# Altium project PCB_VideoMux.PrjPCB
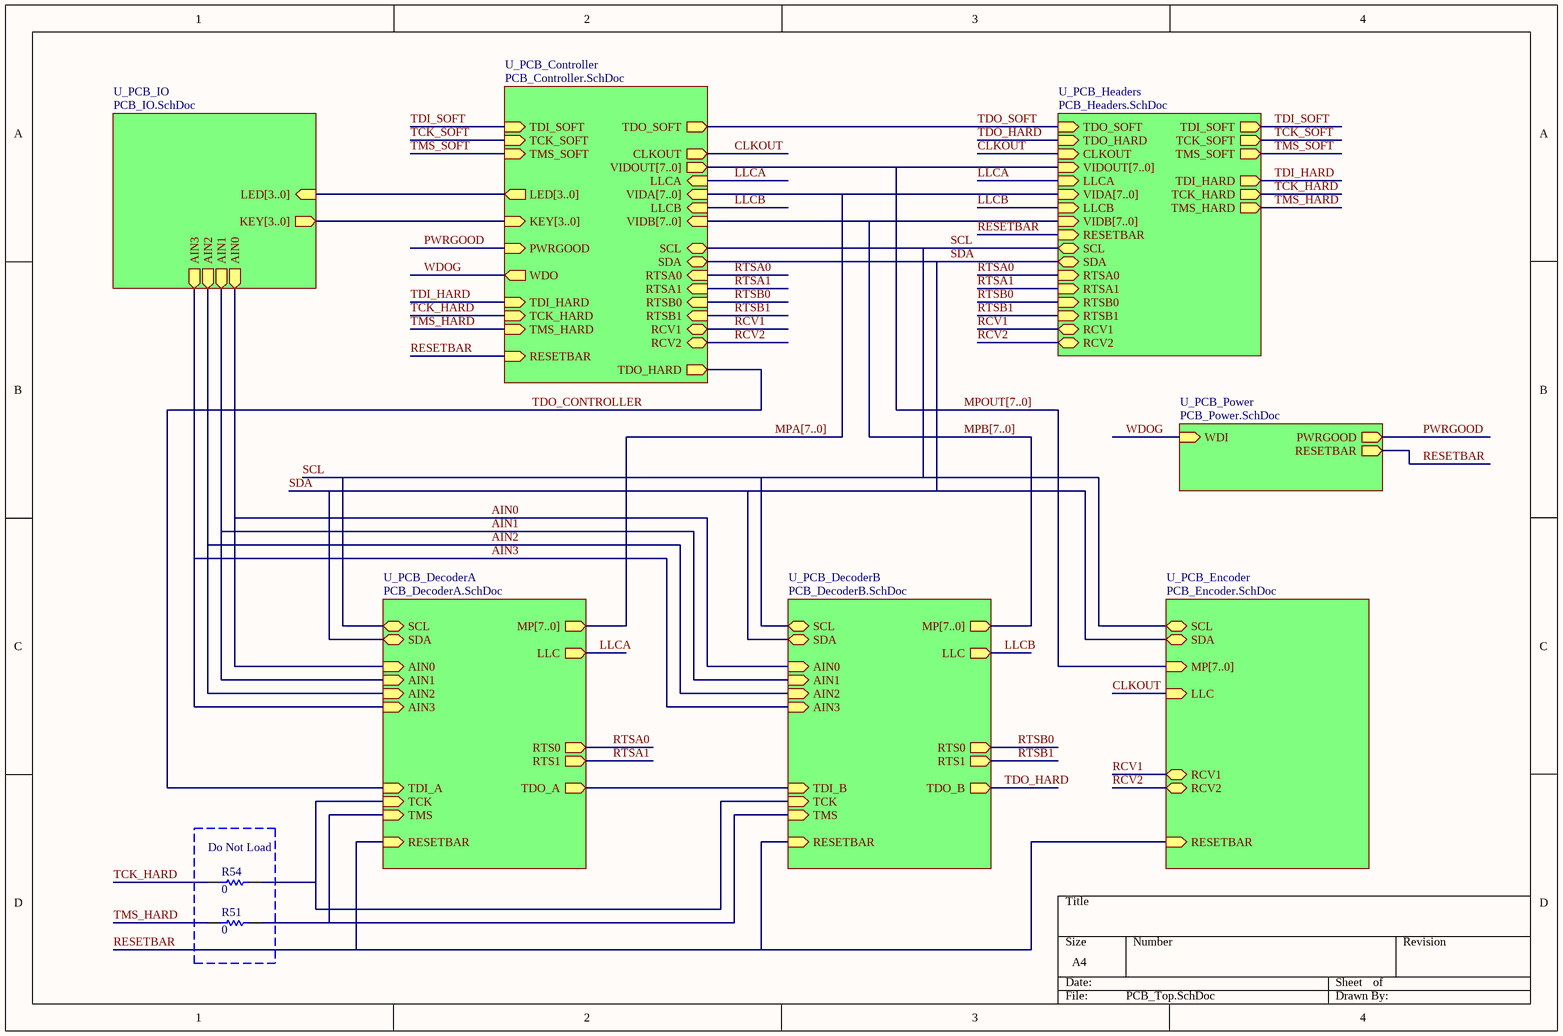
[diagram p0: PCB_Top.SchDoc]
8 sheets, 243 parts. Net scope: hierarchical (ports join the sheet entries above them; power ports are global).
Board file: VideoMuxBoard.PcbDoc
Sheets:
  PCB_Top.SchDoc
    U_PCB_DecoderA = PCB_DecoderA.SchDoc
    U_PCB_DecoderB = PCB_DecoderB.SchDoc
    U_PCB_Headers = PCB_Headers.SchDoc
    U_PCB_Encoder = PCB_Encoder.SchDoc
    U_PCB_IO = PCB_IO.SchDoc
    U_PCB_Controller = PCB_Controller.SchDoc
    U_PCB_Power = PCB_Power.SchDoc

## Sheet PCB_Top.SchDoc
size A4; DocumentNumber: 1; SheetNumber: 1; SheetTotal: 8

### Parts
R51  0  [CC2012-0805]
R54  0  [CC2012-0805]

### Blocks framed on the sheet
Do Not Load: R51 R54

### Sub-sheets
U_PCB_Controller = PCB_Controller.SchDoc: TMS_HARD (in), TMS_SOFT (in), TCK_SOFT (in), TDI_SOFT (in), TDI_HARD (in), TCK_HARD (in), TDO_HARD (out), TDO_SOFT (out), CLKOUT (out), VIDOUT[7..0] (out), LLCA (in), LLCB (in), VIDA[7..0] (in), VIDB[7..0] (in), RESETBAR (in), SCL (bidir), SDA (bidir), RTSA0 (in), RTSA1 (in), RTSB0 (in), RTSB1 (in), RCV1 (bidir), RCV2 (bidir), KEY[3..0] (in), LED[3..0] (out), PWRGOOD (in), WDO (out)
U_PCB_DecoderA = PCB_DecoderA.SchDoc: SCL (bidir), SDA (bidir), TDI_A (in), TCK (in), TMS (in), TDO_A (out), AIN0 (in), AIN1 (in), AIN2 (in), AIN3 (in), MP[7..0] (out), LLC (out), RESETBAR (in), RTS0 (out), RTS1 (out)
U_PCB_DecoderB = PCB_DecoderB.SchDoc: SCL (bidir), SDA (bidir), TDI_B (in), TCK (in), TMS (in), TDO_B (out), AIN0 (in), AIN1 (in), AIN2 (in), AIN3 (in), MP[7..0] (out), LLC (out), RESETBAR (in), RTS0 (out), RTS1 (out)
U_PCB_Encoder = PCB_Encoder.SchDoc: MP[7..0] (in), LLC (in), SCL (bidir), SDA (bidir), RESETBAR (in), RCV1 (bidir), RCV2 (bidir)
U_PCB_Headers = PCB_Headers.SchDoc: TMS_HARD (out), TMS_SOFT (out), TCK_SOFT (out), TDI_SOFT (out), TDI_HARD (out), TCK_HARD (out), TDO_HARD (in), TDO_SOFT (in), CLKOUT (in), VIDOUT[7..0] (in), LLCA (in), LLCB (in), VIDA[7..0] (in), VIDB[7..0] (in), RESETBAR (in), SCL (bidir), SDA (bidir), RTSA0 (in), RTSA1 (in), RTSB0 (in), RTSB1 (in), RCV1 (bidir), RCV2 (bidir)
U_PCB_IO = PCB_IO.SchDoc: AIN0 (out), AIN1 (out), AIN2 (out), AIN3 (out), KEY[3..0] (out), LED[3..0] (in)
U_PCB_Power = PCB_Power.SchDoc: PWRGOOD (out), RESETBAR (out), WDI (in)

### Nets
AIN0: sheet U_PCB_DecoderA/AIN0, sheet U_PCB_DecoderB/AIN0, sheet U_PCB_IO/AIN0
AIN1: sheet U_PCB_DecoderA/AIN1, sheet U_PCB_DecoderB/AIN1, sheet U_PCB_IO/AIN1
AIN2: sheet U_PCB_DecoderA/AIN2, sheet U_PCB_DecoderB/AIN2, sheet U_PCB_IO/AIN2
AIN3: sheet U_PCB_DecoderA/AIN3, sheet U_PCB_DecoderB/AIN3, sheet U_PCB_IO/AIN3
CLKOUT: sheet U_PCB_Headers/CLKOUT, sheet U_PCB_Encoder/LLC, sheet U_PCB_Controller/CLKOUT
LLCA: sheet U_PCB_DecoderA/LLC, sheet U_PCB_Headers/LLCA, sheet U_PCB_Controller/LLCA
LLCB: sheet U_PCB_DecoderB/LLC, sheet U_PCB_Headers/LLCB, sheet U_PCB_Controller/LLCB
PWRGOOD: sheet U_PCB_Controller/PWRGOOD, sheet U_PCB_Power/PWRGOOD
RCV1: sheet U_PCB_Headers/RCV1, sheet U_PCB_Encoder/RCV1, sheet U_PCB_Controller/RCV1
RCV2: sheet U_PCB_Headers/RCV2, sheet U_PCB_Encoder/RCV2, sheet U_PCB_Controller/RCV2
RESETBAR: sheet U_PCB_DecoderA/RESETBAR, sheet U_PCB_DecoderB/RESETBAR, sheet U_PCB_Headers/RESETBAR, sheet U_PCB_Encoder/RESETBAR, sheet U_PCB_Controller/RESETBAR, sheet U_PCB_Power/RESETBAR
RTSA0: sheet U_PCB_DecoderA/RTS0, sheet U_PCB_Headers/RTSA0, sheet U_PCB_Controller/RTSA0
RTSA1: sheet U_PCB_DecoderA/RTS1, sheet U_PCB_Headers/RTSA1, sheet U_PCB_Controller/RTSA1
RTSB0: sheet U_PCB_DecoderB/RTS0, sheet U_PCB_Headers/RTSB0, sheet U_PCB_Controller/RTSB0
RTSB1: sheet U_PCB_DecoderB/RTS1, sheet U_PCB_Headers/RTSB1, sheet U_PCB_Controller/RTSB1
SCL: sheet U_PCB_DecoderA/SCL, sheet U_PCB_DecoderB/SCL, sheet U_PCB_Headers/SCL, sheet U_PCB_Encoder/SCL, sheet U_PCB_Controller/SCL
SDA: sheet U_PCB_DecoderA/SDA, sheet U_PCB_DecoderB/SDA, sheet U_PCB_Headers/SDA, sheet U_PCB_Encoder/SDA, sheet U_PCB_Controller/SDA
TCK: R54.2 ; sheet U_PCB_DecoderA/TCK, sheet U_PCB_DecoderB/TCK
TCK_HARD: R54.1 ; sheet U_PCB_Headers/TCK_HARD, sheet U_PCB_Controller/TCK_HARD
TCK_SOFT: sheet U_PCB_Headers/TCK_SOFT, sheet U_PCB_Controller/TCK_SOFT
TDI_B: sheet U_PCB_DecoderA/TDO_A, sheet U_PCB_DecoderB/TDI_B
TDI_HARD: sheet U_PCB_Headers/TDI_HARD, sheet U_PCB_Controller/TDI_HARD
TDI_SOFT: sheet U_PCB_Headers/TDI_SOFT, sheet U_PCB_Controller/TDI_SOFT
TDO_CONTROLLER: sheet U_PCB_DecoderA/TDI_A, sheet U_PCB_Controller/TDO_HARD
TDO_HARD: sheet U_PCB_DecoderB/TDO_B, sheet U_PCB_Headers/TDO_HARD
TDO_SOFT: sheet U_PCB_Headers/TDO_SOFT, sheet U_PCB_Controller/TDO_SOFT
TMS: R51.2 ; sheet U_PCB_DecoderA/TMS, sheet U_PCB_DecoderB/TMS
TMS_HARD: R51.1 ; sheet U_PCB_Headers/TMS_HARD, sheet U_PCB_Controller/TMS_HARD
TMS_SOFT: sheet U_PCB_Headers/TMS_SOFT, sheet U_PCB_Controller/TMS_SOFT
WDOG: sheet U_PCB_Controller/WDO, sheet U_PCB_Power/WDI

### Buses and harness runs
bus MPA[7..0] = sheet U_PCB_Controller/VIDA[7..0] = sheet U_PCB_DecoderA/MP[7..0] = sheet U_PCB_Headers/VIDA[7..0]
bus MPB[7..0] = sheet U_PCB_Controller/VIDB[7..0] = sheet U_PCB_DecoderB/MP[7..0] = sheet U_PCB_Headers/VIDB[7..0]
bus MPOUT[7..0] = sheet U_PCB_Controller/VIDOUT[7..0] = sheet U_PCB_Encoder/MP[7..0] = sheet U_PCB_Headers/VIDOUT[7..0]
bus sheet U_PCB_Controller/KEY[3..0] = sheet U_PCB_IO/KEY[3..0]
bus sheet U_PCB_Controller/LED[3..0] = sheet U_PCB_IO/LED[3..0]

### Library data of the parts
R51 R54 = RES: Resistor; Fitted: True

## Sheet PCB_DecoderA.SchDoc
size A4; DocumentNumber: 3; SheetNumber: 3; SheetTotal: 8
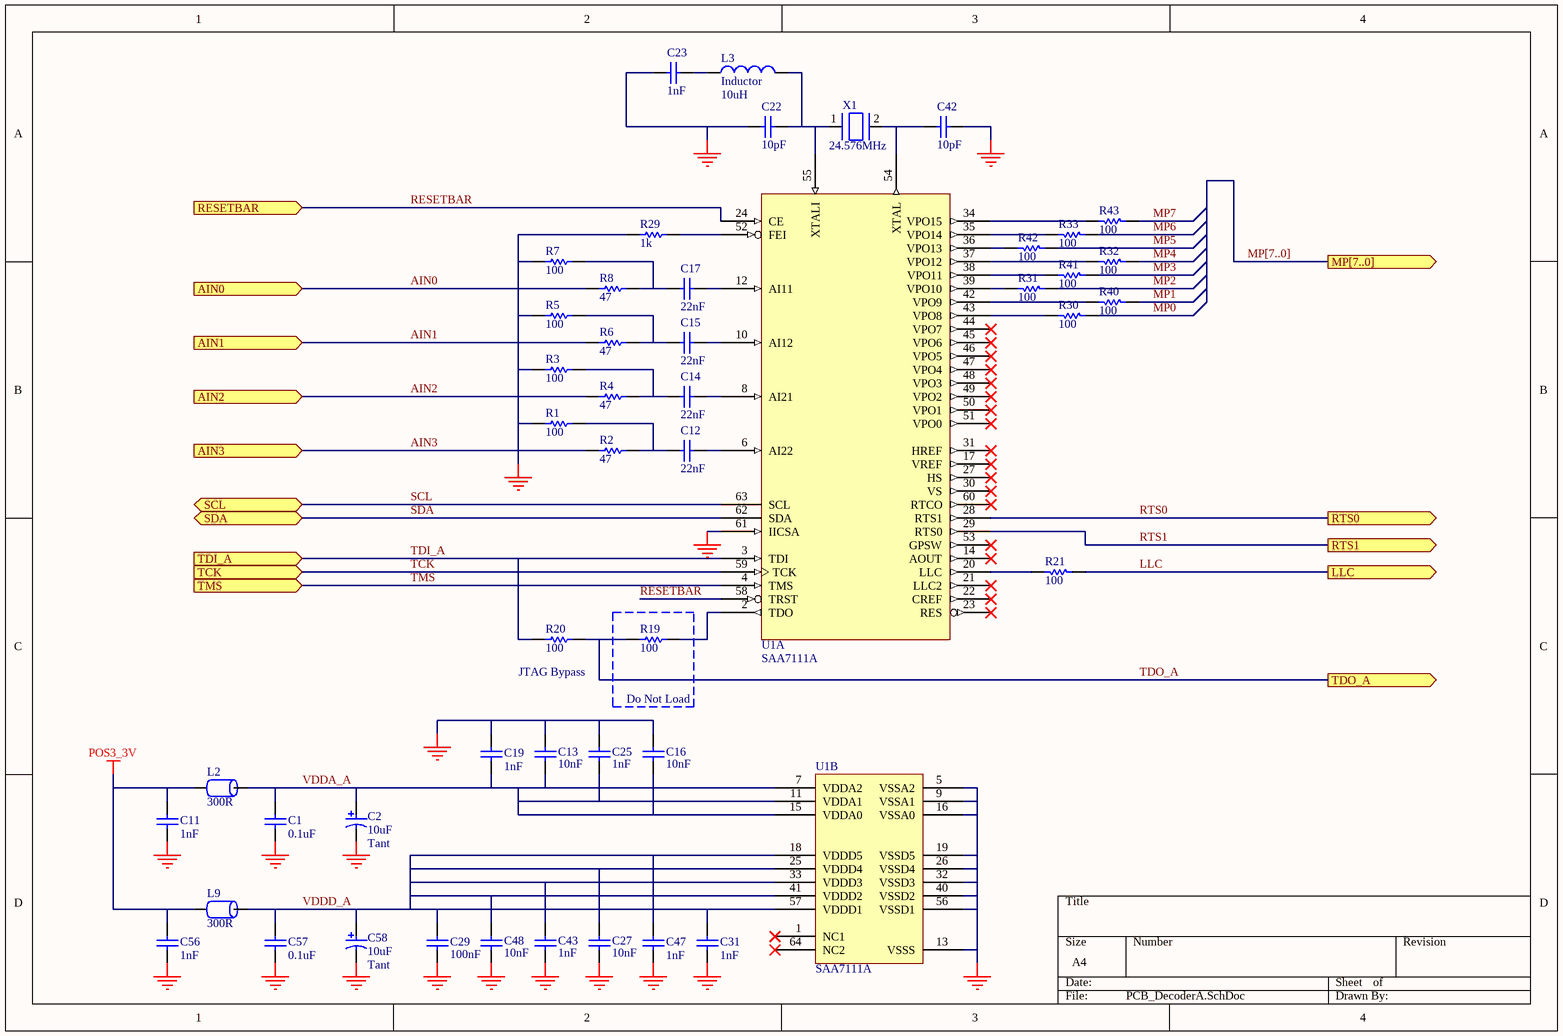
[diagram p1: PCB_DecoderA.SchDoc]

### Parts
C1  0.1uF  [CC2012-0805]
C2  10uF  Capacitor Type: Tant  [MCCT-B]
C11  1nF  [CC2012-0805]
C12  22nF  [CC2012-0805]
C13  10nF  [CC2012-0805]
C14  22nF  [CC2012-0805]
C15  22nF  [CC2012-0805]
C16  10nF  [CC2012-0805]
C17  22nF  [CC2012-0805]
C19  1nF  [CC2012-0805]
C22  10pF  [CC2012-0805]
C23  1nF  [CC2012-0805]
C25  1nF  [CC2012-0805]
C27  10nF  [CC2012-0805]
C29  100nF  [CC2012-0805]
C31  1nF  [CC2012-0805]
C42  10pF  [CC2012-0805]
C43  1nF  [CC2012-0805]
C47  1nF  [CC2012-0805]
C48  10nF  [CC2012-0805]
C56  1nF  [CC2012-0805]
C57  0.1uF  [CC2012-0805]
C58  10uF  Capacitor Type: Tant  [MCCT-B]
L2  300R  [CC2012-0805]
L3  Inductor  value 10uH  [SIMID1008-A]
L9  300R  [CC2012-0805]
R1  100  [CC2012-0805]
R2  47  [CC2012-0805]
R3  100  [CC2012-0805]
R4  47  [CC2012-0805]
R5  100  [CC2012-0805]
R6  47  [CC2012-0805]
R7  100  [CC2012-0805]
R8  47  [CC2012-0805]
R19  100  [CC2012-0805]
R20  100  [CC2012-0805]
R21  100  [CC2012-0805]
R29  1k  [CC2012-0805]
R30  100  [CC2012-0805]
R31  100  [CC2012-0805]
R32  100  [CC2012-0805]
R33  100  [CC2012-0805]
R40  100  [CC2012-0805]
R41  100  [CC2012-0805]
R42  100  [CC2012-0805]
R43  100  [CC2012-0805]
U1  SAA7111A  [QFP14X14_64]  (parts A,B of 2)
X1  24.576MHz  [QC49/SMD]

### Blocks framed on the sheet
Do Not Load: R19

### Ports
AIN0 (in), AIN1 (in), AIN2 (in), AIN3 (in), LLC (out), MP[7..0] (out), RESETBAR (in), RTS0 (out), RTS1 (out), SCL (bidir), SDA (bidir), TCK (in), TDI_A (in), TDO_A (out), TMS (in)

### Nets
GND: C1.2 C2.2 C11.2 C13.1 C16.1 C19.1 C22.1 C23.1 C25.1 C27.2 C29.2 C31.2 C42.2 C43.2 C47.2 C48.2 C56.2 C57.2 C58.2 R1.1 R3.1 R5.1 R7.1 R29.1 U1.5(VSSA2) U1.9(VSSA1) U1.13(VSSS) U1.16(VSSA0) U1.19(VSSD5) U1.26(VSSD4) U1.32(VSSD3) U1.40(VSSD2) U1.56(VSSD1) U1.61(IICSA)
POS3_3V: C11.1 C56.1 L2.1 L9.1
AIN0: R8.1 ; port AIN0
AIN1: R6.1 ; port AIN1
AIN2: R4.1 ; port AIN2
AIN3: R2.1 ; port AIN3
LLC: R21.1 ; port LLC  [project net LLCA]
MP0: R30.1  [project net MPA0]
MP1: R40.1  [project net MPA1]
MP2: R31.1  [project net MPA2]
MP3: R41.1  [project net MPA3]
MP4: R32.1  [project net MPA4]
MP5: R42.1  [project net MPA5]
MP6: R33.1  [project net MPA6]
MP7: R43.1  [project net MPA7]
RESETBAR: U1.24(CE) U1.58(TRST) ; port RESETBAR
RTS0: U1.28(RTS1) ; port RTS0  [project net RTSA0]
RTS1: U1.29(RTS0) ; port RTS1  [project net RTSA1]
SCL: U1.63(SCL) ; port SCL
SDA: U1.62(SDA) ; port SDA
TCK: U1.59(TCK) ; port TCK
TDI_A: R20.1 U1.3(TDI) ; port TDI_A  [project net TDO_CONTROLLER]
TDO_A: R19.1 R20.2 ; port TDO_A  [project net TDI_B]
TMS: U1.4(TMS) ; port TMS
VDDA_A: C1.1 C2.1 C13.2 C16.2 C19.2 C25.2 L2.2 U1.7(VDDA2) U1.11(VDDA1) U1.15(VDDA0)
VDDD_A: C27.1 C29.1 C31.1 C43.1 C47.1 C48.1 C57.1 C58.1 L9.2 U1.18(VDDD5) U1.25(VDDD4) U1.33(VDDD3) U1.41(VDDD2) U1.57(VDDD1)
NetC12_1: C12.1 R1.2 R2.2
NetC12_2: C12.2 U1.6(AI22)
NetC14_1: C14.1 R3.2 R4.2
NetC14_2: C14.2 U1.8(AI21)
NetC15_1: C15.1 R5.2 R6.2
NetC15_2: C15.2 U1.10(AI12)
NetC17_1: C17.1 R7.2 R8.2
NetC17_2: C17.2 U1.12(AI11)
NetC22_2: C22.2 L3.2 U1.55(XTALI) X1.1
NetC23_2: C23.2 L3.1
NetC42_1: C42.1 U1.54(XTAL) X1.2
NetR19_2: R19.2 U1.2(TDO)
NetR21_2: R21.2 U1.20(LLC)
NetR29_2: R29.2 U1.52(FEI)
NetR30_2: R30.2 U1.43(VPO8)
NetR31_2: R31.2 U1.39(VPO10)
NetR32_2: R32.2 U1.37(VPO12)
NetR33_2: R33.2 U1.35(VPO14)
NetR40_2: R40.2 U1.42(VPO9)
NetR41_2: R41.2 U1.38(VPO11)
NetR42_2: R42.2 U1.36(VPO13)
NetR43_2: R43.2 U1.34(VPO15)

Not connected (* = marked no-connect by the designer): U1 1(NC1)* 14(AOUT)* 17(VREF)* 21(LLC2)* 22(CREF)* 23(RES)* 27(HS)* 30(VS)* 31(HREF)* 44(VPO7)* 45(VPO6)* 46(VPO5)* 47(VPO4)* 48(VPO3)* 49(VPO2)* 50(VPO1)* 51(VPO0)* 53(GPSW)* 60(RTCO)* 64(NC2)*

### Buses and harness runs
bus MP[7..0] = port MP[7..0]

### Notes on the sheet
- (near R20) JTAG Bypass

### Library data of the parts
C1 C11-C17 C19 C22 C23 C25 C27 C29 C31 C42 C43 C47 C48 C56 C57 = CAP: Capacitor; Fitted: True
C2 C58 = CAP_POLAR: Polar Capacitor; Fitted: True
L2 L9 = FERRITE_BEAD: BMB Series Ferrite Chip Bead
L3 = Inductor: Manufacturer: Generic Components; Class I: Passive
R1-R8 R19-R21 R29-R33 R40-R43 = RES: Resistor; Fitted: True
U1 = SAA7111A: Philips Enhanced Video Input Processor
X1 = CRYSTAL

## Sheet PCB_DecoderB.SchDoc
size A4; DocumentNumber: 4; SheetNumber: 4; SheetTotal: 8
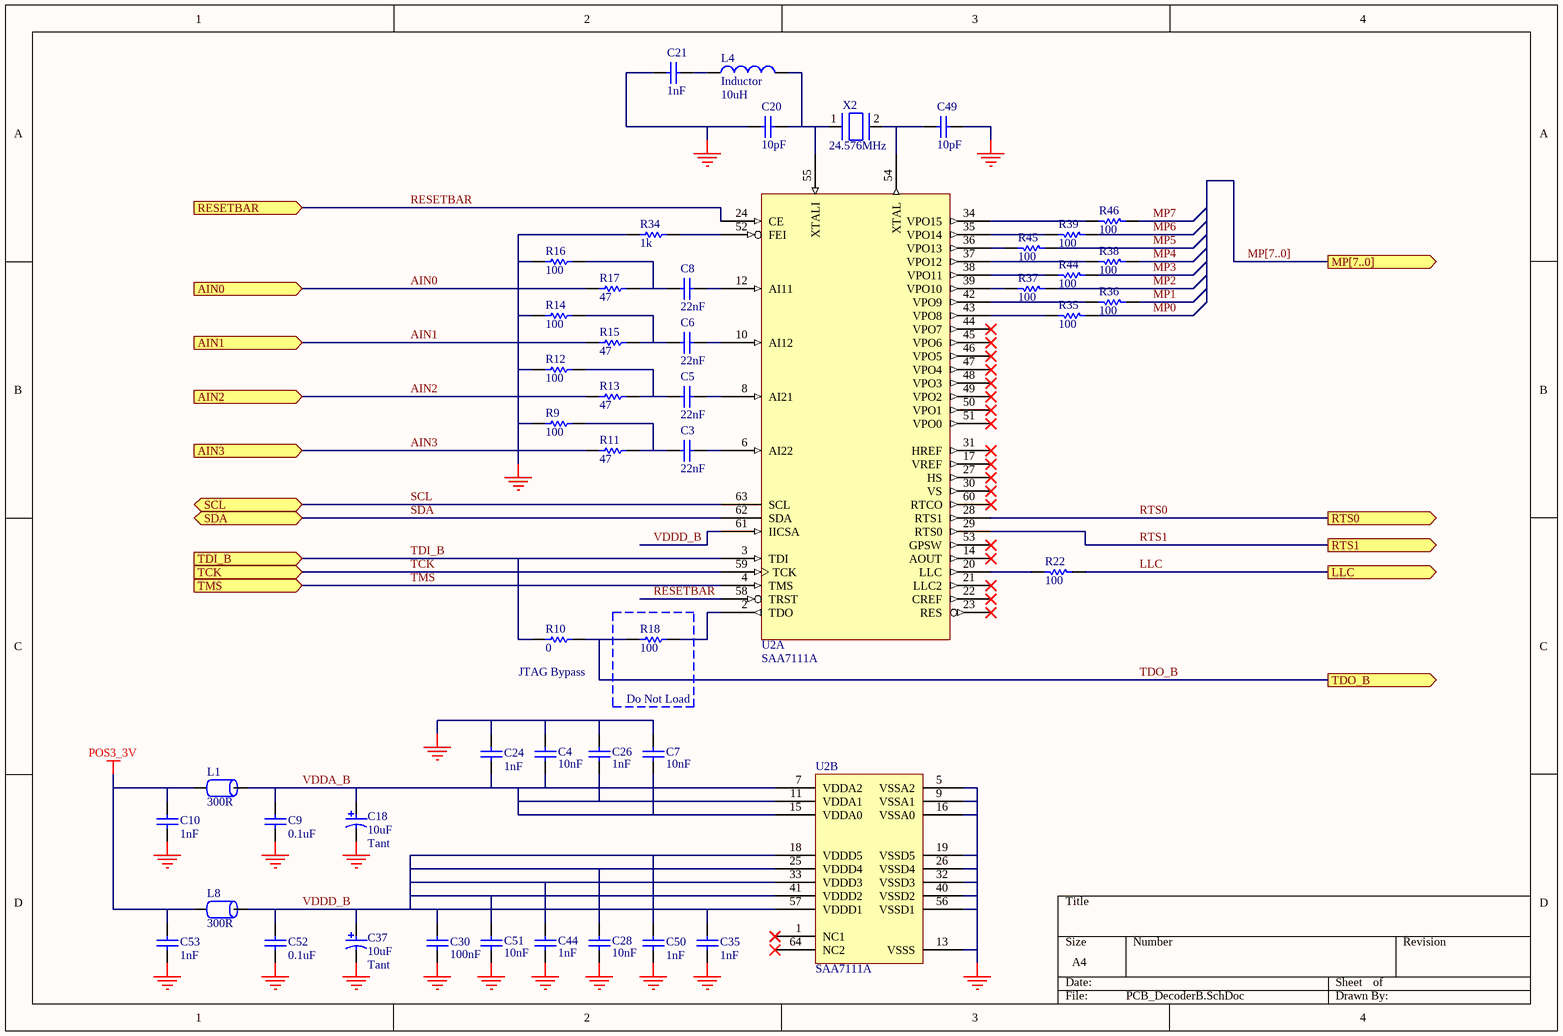
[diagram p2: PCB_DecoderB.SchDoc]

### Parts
C3  22nF  [CC2012-0805]
C4  10nF  [CC2012-0805]
C5  22nF  [CC2012-0805]
C6  22nF  [CC2012-0805]
C7  10nF  [CC2012-0805]
C8  22nF  [CC2012-0805]
C9  0.1uF  [CC2012-0805]
C10  1nF  [CC2012-0805]
C18  10uF  Capacitor Type: Tant  [MCCT-B]
C20  10pF  [CC2012-0805]
C21  1nF  [CC2012-0805]
C24  1nF  [CC2012-0805]
C26  1nF  [CC2012-0805]
C28  10nF  [CC2012-0805]
C30  100nF  [CC2012-0805]
C35  1nF  [CC2012-0805]
C37  10uF  Capacitor Type: Tant  [MCCT-B]
C44  1nF  [CC2012-0805]
C49  10pF  [CC2012-0805]
C50  1nF  [CC2012-0805]
C51  10nF  [CC2012-0805]
C52  0.1uF  [CC2012-0805]
C53  1nF  [CC2012-0805]
L1  300R  [CC2012-0805]
L4  Inductor  value 10uH  [SIMID1008-A]
L8  300R  [CC2012-0805]
R9  100  [CC2012-0805]
R10  0  [CC2012-0805]
R11  47  [CC2012-0805]
R12  100  [CC2012-0805]
R13  47  [CC2012-0805]
R14  100  [CC2012-0805]
R15  47  [CC2012-0805]
R16  100  [CC2012-0805]
R17  47  [CC2012-0805]
R18  100  [CC2012-0805]
R22  100  [CC2012-0805]
R34  1k  [CC2012-0805]
R35  100  [CC2012-0805]
R36  100  [CC2012-0805]
R37  100  [CC2012-0805]
R38  100  [CC2012-0805]
R39  100  [CC2012-0805]
R44  100  [CC2012-0805]
R45  100  [CC2012-0805]
R46  100  [CC2012-0805]
U2  SAA7111A  [QFP14X14_64]  (parts A,B of 2)
X2  24.576MHz  [QC49/SMD]

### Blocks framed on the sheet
Do Not Load: R18

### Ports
AIN0 (in), AIN1 (in), AIN2 (in), AIN3 (in), LLC (out), MP[7..0] (out), RESETBAR (in), RTS0 (out), RTS1 (out), SCL (bidir), SDA (bidir), TCK (in), TDI_B (in), TDO_B (out), TMS (in)

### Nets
GND: C4.1 C7.1 C9.2 C10.2 C18.2 C20.1 C21.1 C24.1 C26.1 C28.2 C30.2 C35.2 C37.2 C44.2 C49.2 C50.2 C51.2 C52.2 C53.2 R9.1 R12.1 R14.1 R16.1 R34.1 U2.5(VSSA2) U2.9(VSSA1) U2.13(VSSS) U2.16(VSSA0) U2.19(VSSD5) U2.26(VSSD4) U2.32(VSSD3) U2.40(VSSD2) U2.56(VSSD1)
POS3_3V: C10.1 C53.1 L1.1 L8.1
AIN0: R17.1 ; port AIN0
AIN1: R15.1 ; port AIN1
AIN2: R13.1 ; port AIN2
AIN3: R11.1 ; port AIN3
LLC: R22.1 ; port LLC  [project net LLCB]
MP0: R35.1  [project net MPB0]
MP1: R36.1  [project net MPB1]
MP2: R37.1  [project net MPB2]
MP3: R44.1  [project net MPB3]
MP4: R38.1  [project net MPB4]
MP5: R45.1  [project net MPB5]
MP6: R39.1  [project net MPB6]
MP7: R46.1  [project net MPB7]
RESETBAR: U2.24(CE) U2.58(TRST) ; port RESETBAR
RTS0: U2.28(RTS1) ; port RTS0  [project net RTSB0]
RTS1: U2.29(RTS0) ; port RTS1  [project net RTSB1]
SCL: U2.63(SCL) ; port SCL
SDA: U2.62(SDA) ; port SDA
TCK: U2.59(TCK) ; port TCK
TDI_B: R10.1 U2.3(TDI) ; port TDI_B
TDO_B: R10.2 R18.1 ; port TDO_B  [project net TDO_HARD]
TMS: U2.4(TMS) ; port TMS
VDDA_B: C4.2 C7.2 C9.1 C18.1 C24.2 C26.2 L1.2 U2.7(VDDA2) U2.11(VDDA1) U2.15(VDDA0)
VDDD_B: C28.1 C30.1 C35.1 C37.1 C44.1 C50.1 C51.1 C52.1 L8.2 U2.18(VDDD5) U2.25(VDDD4) U2.33(VDDD3) U2.41(VDDD2) U2.57(VDDD1) U2.61(IICSA)
NetC3_1: C3.1 R9.2 R11.2
NetC3_2: C3.2 U2.6(AI22)
NetC5_1: C5.1 R12.2 R13.2
NetC5_2: C5.2 U2.8(AI21)
NetC6_1: C6.1 R14.2 R15.2
NetC6_2: C6.2 U2.10(AI12)
NetC8_1: C8.1 R16.2 R17.2
NetC8_2: C8.2 U2.12(AI11)
NetC20_2: C20.2 L4.2 U2.55(XTALI) X2.1
NetC21_2: C21.2 L4.1
NetC49_1: C49.1 U2.54(XTAL) X2.2
NetR18_2: R18.2 U2.2(TDO)
NetR22_2: R22.2 U2.20(LLC)
NetR34_2: R34.2 U2.52(FEI)
NetR35_2: R35.2 U2.43(VPO8)
NetR36_2: R36.2 U2.42(VPO9)
NetR37_2: R37.2 U2.39(VPO10)
NetR38_2: R38.2 U2.37(VPO12)
NetR39_2: R39.2 U2.35(VPO14)
NetR44_2: R44.2 U2.38(VPO11)
NetR45_2: R45.2 U2.36(VPO13)
NetR46_2: R46.2 U2.34(VPO15)

Not connected (* = marked no-connect by the designer): U2 1(NC1)* 14(AOUT)* 17(VREF)* 21(LLC2)* 22(CREF)* 23(RES)* 27(HS)* 30(VS)* 31(HREF)* 44(VPO7)* 45(VPO6)* 46(VPO5)* 47(VPO4)* 48(VPO3)* 49(VPO2)* 50(VPO1)* 51(VPO0)* 53(GPSW)* 60(RTCO)* 64(NC2)*

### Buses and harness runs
bus MP[7..0] = port MP[7..0]

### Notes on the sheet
- (near R10) JTAG Bypass

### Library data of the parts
C3-C10 C20 C21 C24 C26 C28 C30 C35 C44 C49-C53 = CAP: Capacitor; Fitted: True
C18 C37 = CAP_POLAR: Polar Capacitor; Fitted: True
L1 L8 = FERRITE_BEAD: BMB Series Ferrite Chip Bead
L4 = Inductor: as L3 on sheet PCB_DecoderA
R9-R18 R22 R34-R39 R44-R46 = RES: Resistor; Fitted: True
U2 = SAA7111A: Philips Enhanced Video Input Processor
X2 = CRYSTAL

## Sheet PCB_Headers.SchDoc
size A4; DocumentNumber: 6; SheetNumber: 6; SheetTotal: 8
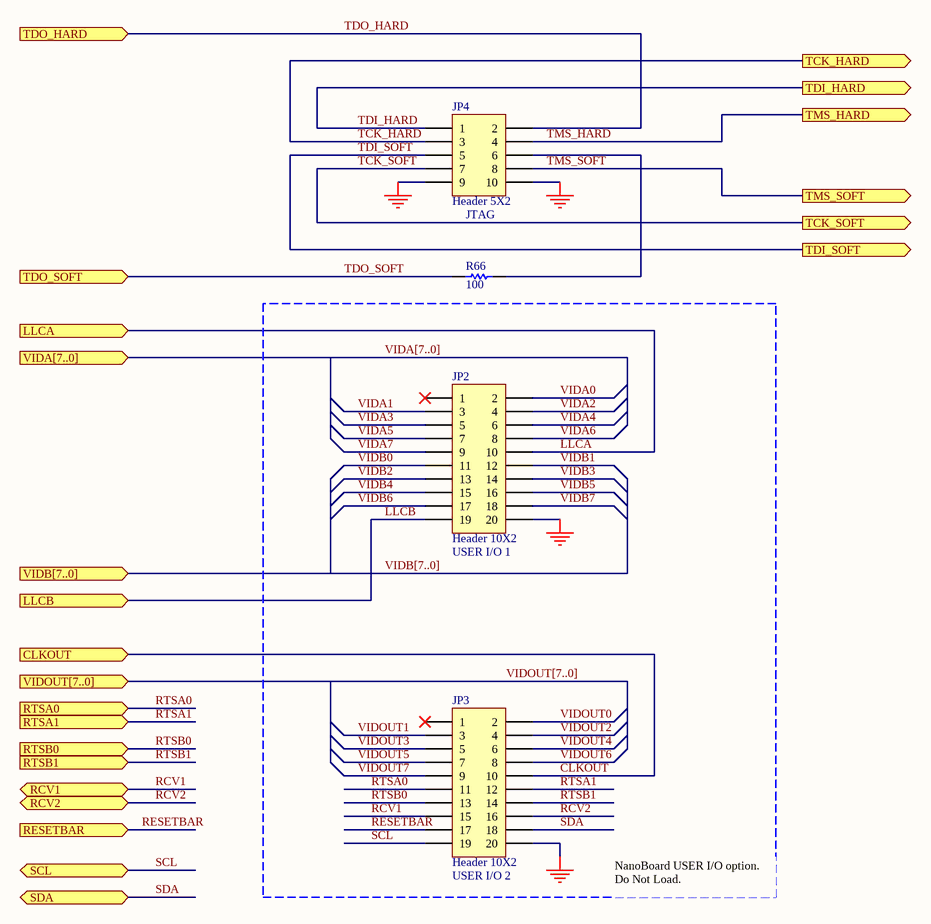
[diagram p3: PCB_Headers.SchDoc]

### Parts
JP2  Header 10X2  [HDR2X10]
JP3  Header 10X2  [HDR2X10]
JP4  Header 5X2  [HDR2X5]
R66  100  [CC2012-0805]

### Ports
CLKOUT (in), LLCA (in), LLCB (in), RCV1 (bidir), RCV2 (bidir), RESETBAR (in), RTSA0 (in), RTSA1 (in), RTSB0 (in), RTSB1 (in), SCL (bidir), SDA (bidir), TCK_HARD (out), TCK_SOFT (out), TDI_HARD (out), TDI_SOFT (out), TDO_HARD (in), TDO_SOFT (in), TMS_HARD (out), TMS_SOFT (out), VIDA[7..0] (in), VIDB[7..0] (in), VIDOUT[7..0] (in)

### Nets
GND: JP2.20 JP3.20 JP4.9 JP4.10
CLKOUT: JP3.10 ; port CLKOUT
LLCA: JP2.10 ; port LLCA
LLCB: JP2.19 ; port LLCB
RCV1: JP3.15 ; port RCV1
RCV2: JP3.16 ; port RCV2
RESETBAR: JP3.17 ; port RESETBAR
RTSA0: JP3.11 ; port RTSA0
RTSA1: JP3.12 ; port RTSA1
RTSB0: JP3.13 ; port RTSB0
RTSB1: JP3.14 ; port RTSB1
SCL: JP3.19 ; port SCL
SDA: JP3.18 ; port SDA
TCK_HARD: JP4.3 ; port TCK_HARD
TCK_SOFT: JP4.7 ; port TCK_SOFT
TDI_HARD: JP4.1 ; port TDI_HARD
TDI_SOFT: JP4.5 ; port TDI_SOFT
TDO_HARD: JP4.2 ; port TDO_HARD
TDO_SOFT: R66.1 ; port TDO_SOFT
TMS_HARD: JP4.4 ; port TMS_HARD
TMS_SOFT: JP4.8 ; port TMS_SOFT
VIDA0: JP2.2  [project net MPA0]
VIDA1: JP2.3  [project net MPA1]
VIDA2: JP2.4  [project net MPA2]
VIDA3: JP2.5  [project net MPA3]
VIDA4: JP2.6  [project net MPA4]
VIDA5: JP2.7  [project net MPA5]
VIDA6: JP2.8  [project net MPA6]
VIDA7: JP2.9  [project net MPA7]
VIDB0: JP2.11  [project net MPB0]
VIDB1: JP2.12  [project net MPB1]
VIDB2: JP2.13  [project net MPB2]
VIDB3: JP2.14  [project net MPB3]
VIDB4: JP2.15  [project net MPB4]
VIDB5: JP2.16  [project net MPB5]
VIDB6: JP2.17  [project net MPB6]
VIDB7: JP2.18  [project net MPB7]
VIDOUT0: JP3.2  [project net MPOUT0]
VIDOUT1: JP3.3  [project net MPOUT1]
VIDOUT2: JP3.4  [project net MPOUT2]
VIDOUT3: JP3.5  [project net MPOUT3]
VIDOUT4: JP3.6  [project net MPOUT4]
VIDOUT5: JP3.7  [project net MPOUT5]
VIDOUT6: JP3.8  [project net MPOUT6]
VIDOUT7: JP3.9  [project net MPOUT7]
NetJP4_6: JP4.6 R66.2

Not connected (* = marked no-connect by the designer): JP2 1*; JP3 1*

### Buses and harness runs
bus VIDA[7..0] = port VIDA[7..0]
bus VIDB[7..0] = port VIDB[7..0]
bus VIDOUT[7..0] = port VIDOUT[7..0]

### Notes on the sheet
- (near JP4) JTAG
- (near JP2) USER I/O 1
- (near JP3) USER I/O 2
- NanoBoard USER I/O option. Do Not Load.

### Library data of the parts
JP2 JP3 = Header 10X2: Header, 10-Pin, Dual row; Manufacturer: Generic Components; Class I: Connector
JP4 = Header 5X2: Header, 5-Pin, Dual row; Manufacturer: Generic Components; Class I: Connector
R66 = RES: Resistor; Fitted: True

## Sheet PCB_Encoder.SchDoc
size A4; DocumentNumber: 2; SheetNumber: 2; SheetTotal: 8
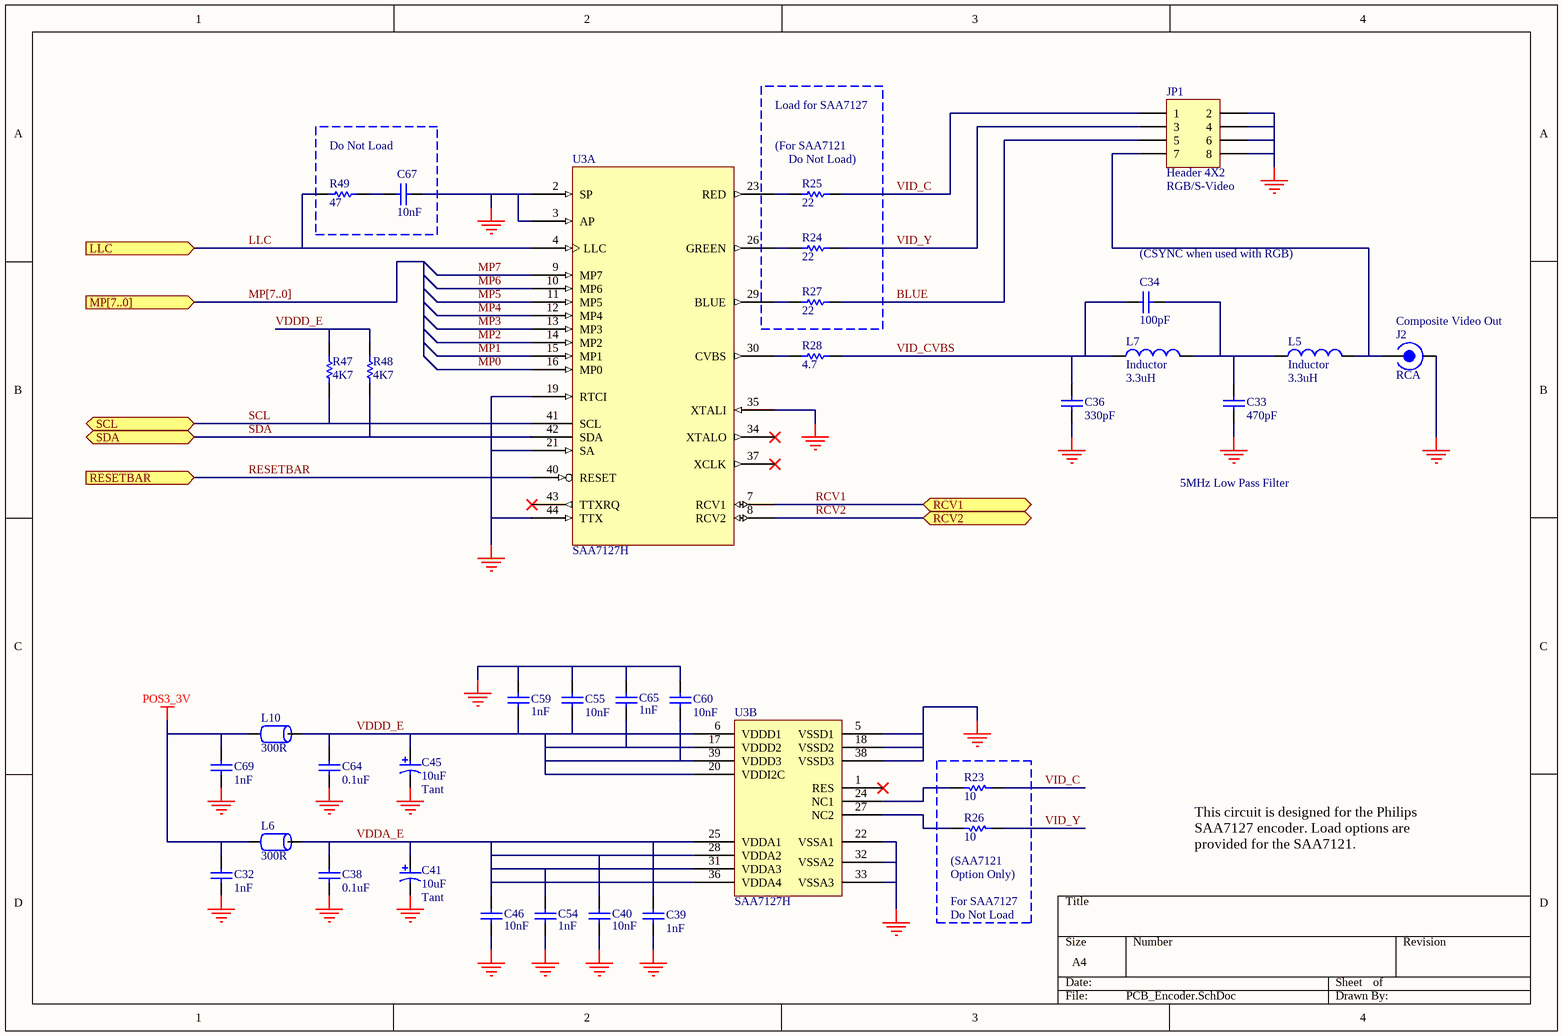
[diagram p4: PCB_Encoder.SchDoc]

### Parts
C32  1nF  [CC2012-0805]
C33  470pF  [CC2012-0805]
C34  100pF  [CC2012-0805]
C36  330pF  [CC2012-0805]
C38  0.1uF  [CC2012-0805]
C39  1nF  [CC2012-0805]
C40  10nF  [CC2012-0805]
C41  10uF  Capacitor Type: Tant  [MCCT-B]
C45  10uF  Capacitor Type: Tant  [MCCT-B]
C46  10nF  [CC2012-0805]
C54  1nF  [CC2012-0805]
C55  10nF  [CC2012-0805]
C59  1nF  [CC2012-0805]
C60  10nF  [CC2012-0805]
C64  0.1uF  [CC2012-0805]
C65  1nF  [CC2012-0805]
C67  10nF  [CC2012-0805]
C69  1nF  [CC2012-0805]
J2  RCA  [RCA_MR551L]
JP1  Header 4X2  [HDR2X4]
L5  Inductor  value 3.3uH  [CC2012-0805]
L6  300R  [CC2012-0805]
L7  Inductor  value 3.3uH  [CC2012-0805]
L10  300R  [CC2012-0805]
R23  10  [CC2012-0805]
R24  22  [CC2012-0805]
R25  22  [CC2012-0805]
R26  10  [CC2012-0805]
R27  22  [CC2012-0805]
R28  4.7  [CC2012-0805]
R47  4K7  [CC2012-0805]
R48  4K7  [CC2012-0805]
R49  47  [CC2012-0805]
U3  SAA7127H  [QFP10X10_44]  (parts A,B of 2)

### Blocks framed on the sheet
Do Not Load: C67 R49

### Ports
LLC (in), MP[7..0] (in), RCV1 (bidir), RCV2 (bidir), RESETBAR (in), SCL (bidir), SDA (bidir)

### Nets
GND: C32.2 C33.2 C36.2 C38.2 C39.2 C40.2 C41.2 C45.2 C46.2 C54.2 C55.1 C59.1 C60.1 C64.2 C65.1 C67.2 C69.2 J2.2 JP1.2 JP1.4 JP1.6 JP1.8 U3.2(SP) U3.3(AP) U3.5(VSSD1) U3.18(VSSD2) U3.19(RTCI) U3.21(SA) U3.22(VSSA1) U3.32(VSSA2) U3.33(VSSA3) U3.35(XTALI) U3.38(VSSD3) U3.44(TTX)
POS3_3V: C32.1 C69.1 L6.1 L10.1
BLUE: JP1.5 R27.2
LLC: R49.1 U3.4(LLC) ; port LLC  [project net CLKOUT]
MP0: U3.16(MP0)  [project net MPOUT0]
MP1: U3.15(MP1)  [project net MPOUT1]
MP2: U3.14(MP2)  [project net MPOUT2]
MP3: U3.13(MP3)  [project net MPOUT3]
MP4: U3.12(MP4)  [project net MPOUT4]
MP5: U3.11(MP5)  [project net MPOUT5]
MP6: U3.10(MP6)  [project net MPOUT6]
MP7: U3.9(MP7)  [project net MPOUT7]
RCV1: U3.7(RCV1) ; port RCV1
RCV2: U3.8(RCV2) ; port RCV2
RESETBAR: U3.40(RESET) ; port RESETBAR
SCL: R47.1 U3.41(SCL) ; port SCL
SDA: R48.1 U3.42(SDA) ; port SDA
VDDA_E: C38.1 C39.1 C40.1 C41.1 C46.1 C54.1 L6.2 U3.25(VDDA1) U3.28(VDDA2) U3.31(VDDA3) U3.36(VDDA4)
VDDD_E: C45.1 C55.2 C59.2 C60.2 C64.1 C65.2 L10.2 R47.2 R48.2 U3.6(VDDD1) U3.17(VDDD2) U3.20(VDDI2C) U3.39(VDDD3)
VID_C: JP1.1 R23.2 R25.2
VID_CVBS: C34.1 C36.1 L7.1 R28.2
VID_Y: JP1.3 R24.2 R26.2
NetC33_1: C33.1 C34.2 L5.1 L7.2
NetC67_1: C67.1 R49.2
NetJ2_1: J2.1 JP1.7 L5.2
NetR23_1: R23.1 U3.24(NC1)
NetR24_1: R24.1 U3.26(GREEN)
NetR25_1: R25.1 U3.23(RED)
NetR26_1: R26.1 U3.27(NC2)
NetR27_1: R27.1 U3.29(BLUE)
NetR28_1: R28.1 U3.30(CVBS)

Not connected (* = marked no-connect by the designer): U3 1(RES)* 34(XTALO)* 37(XCLK)* 43(TTXRQ)*

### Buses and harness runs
bus MP[7..0] = port MP[7..0]

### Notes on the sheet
- Load for SAA7127
- (For SAA7121
- (near R25) Do Not Load)
- (near JP1) RGB/S-Video
- (near C34) (CSYNC when used with RGB)
- (near J2) Composite Video Out
- 5MHz Low Pass Filter
- (near R26) (SAA7121
- (near R26) Option Only)
- For SAA7127
- Do Not Load
- This circuit is designed for the Philips SAA7127 encoder. Load options are provided for the SAA7121.

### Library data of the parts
C32-C34 C36 C38-C40 C46 C54 C55 C59 C60 C64 C65 C67 C69 = CAP: Capacitor; Fitted: True
C41 C45 = CAP_POLAR: Polar Capacitor; Fitted: True
J2 = RCA: RCA Socket
JP1 = Header 4X2: Header, 4-Pin, Dual row; Manufacturer: Generic Components; Class I: Connector
L5 L7 = Inductor: as L3 on sheet PCB_DecoderA
L6 L10 = FERRITE_BEAD: BMB Series Ferrite Chip Bead
R23-R28 R47-R49 = RES: Resistor; Fitted: True
U3 = SAA7127H: Philips Digital Video Encoder

## Sheet PCB_IO.SchDoc
size A4; DocumentNumber: 7; SheetNumber: 7; SheetTotal: 8
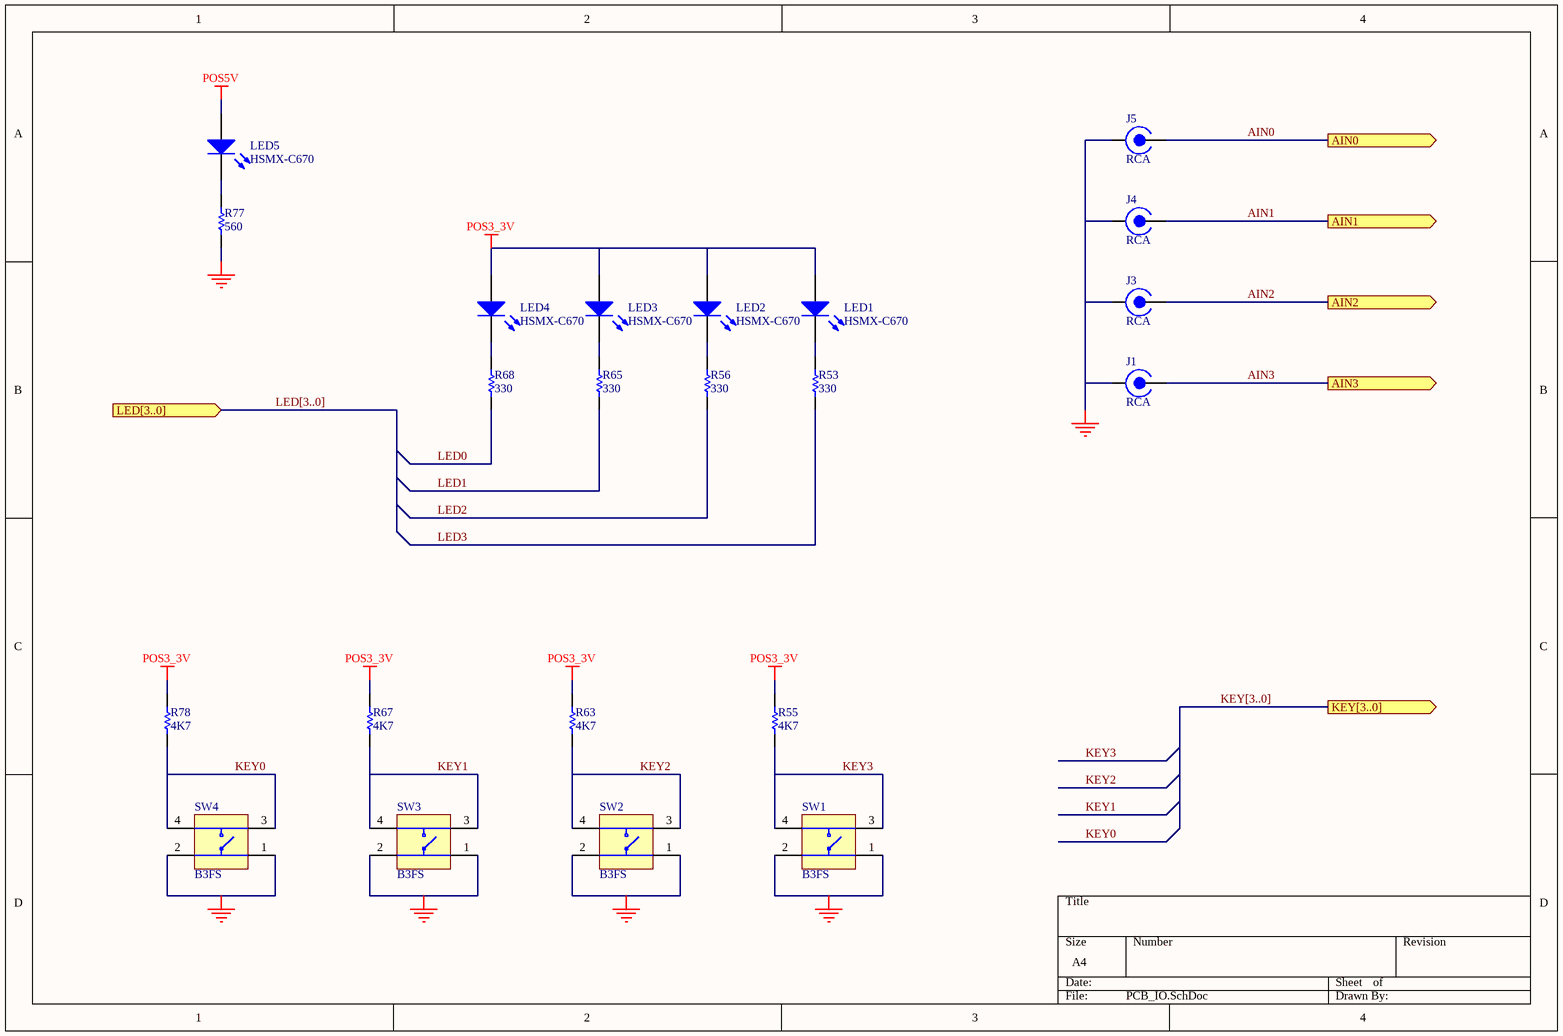
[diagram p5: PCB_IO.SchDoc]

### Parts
J1  RCA  [RCA_MR551L]
J3  RCA  [RCA_MR551L]
J4  RCA  [RCA_MR551L]
J5  RCA  [RCA_MR551L]
LED1  HSMX-C670  [SMD _LED]
LED2  HSMX-C670  [SMD _LED]
LED3  HSMX-C670  [SMD _LED]
LED4  HSMX-C670  [SMD _LED]
LED5  HSMX-C670  [SMD _LED]
R53  330  [CC2012-0805]
R55  4K7  [CC2012-0805]
R56  330  [CC2012-0805]
R63  4K7  [CC2012-0805]
R65  330  [CC2012-0805]
R67  4K7  [CC2012-0805]
R68  330  [CC2012-0805]
R77  560  [CC2012-0805]
R78  4K7  [CC2012-0805]
SW1  B3FS  [B3FS_SWITCH]
SW2  B3FS  [B3FS_SWITCH]
SW3  B3FS  [B3FS_SWITCH]
SW4  B3FS  [B3FS_SWITCH]

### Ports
AIN0 (out), AIN1 (out), AIN2 (out), AIN3 (out), KEY[3..0] (out), LED[3..0] (in)

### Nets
GND: J1.2 J3.2 J4.2 J5.2 R77.2 SW1.1 SW1.2 SW2.1 SW2.2 SW3.1 SW3.2 SW4.1 SW4.2
POS3_3V: LED1.1(A) LED2.1(A) LED3.1(A) LED4.1(A) R55.1 R63.1 R67.1 R78.1
POS5V: LED5.1(A)
AIN0: J5.1 ; port AIN0
AIN1: J4.1 ; port AIN1
AIN2: J3.1 ; port AIN2
AIN3: J1.1 ; port AIN3
KEY0: R78.2 SW4.3 SW4.4
KEY1: R67.2 SW3.3 SW3.4
KEY2: R63.2 SW2.3 SW2.4
KEY3: R55.2 SW1.3 SW1.4
LED0: R68.2
LED1: R65.2
LED2: R56.2
LED3: R53.2
NetLED1_2: LED1.2(K) R53.1
NetLED2_2: LED2.2(K) R56.1
NetLED3_2: LED3.2(K) R65.1
NetLED4_2: LED4.2(K) R68.1
NetLED5_2: LED5.2(K) R77.1

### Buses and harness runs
bus KEY[3..0] = port KEY[3..0]
bus LED[3..0] = port LED[3..0]

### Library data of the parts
J1 J3-J5 = RCA: RCA Socket
LED1-LED5 = HSMX-C670: Typical RED GaAs SMD LED Agilent make; Manufacturer: Generic Components; Class I: Optoelectronic; Fitted: True
R53 R55 R56 R63 R65 R67 R68 R77 R78 = RES: Resistor; Fitted: True
SW1-SW4 = B3FS: SPNA SMD Keyboard Switch; Fitted: True

## Sheet PCB_Controller.SchDoc
size A3; DocumentNumber: 8; SheetNumber: 8; SheetTotal: 8
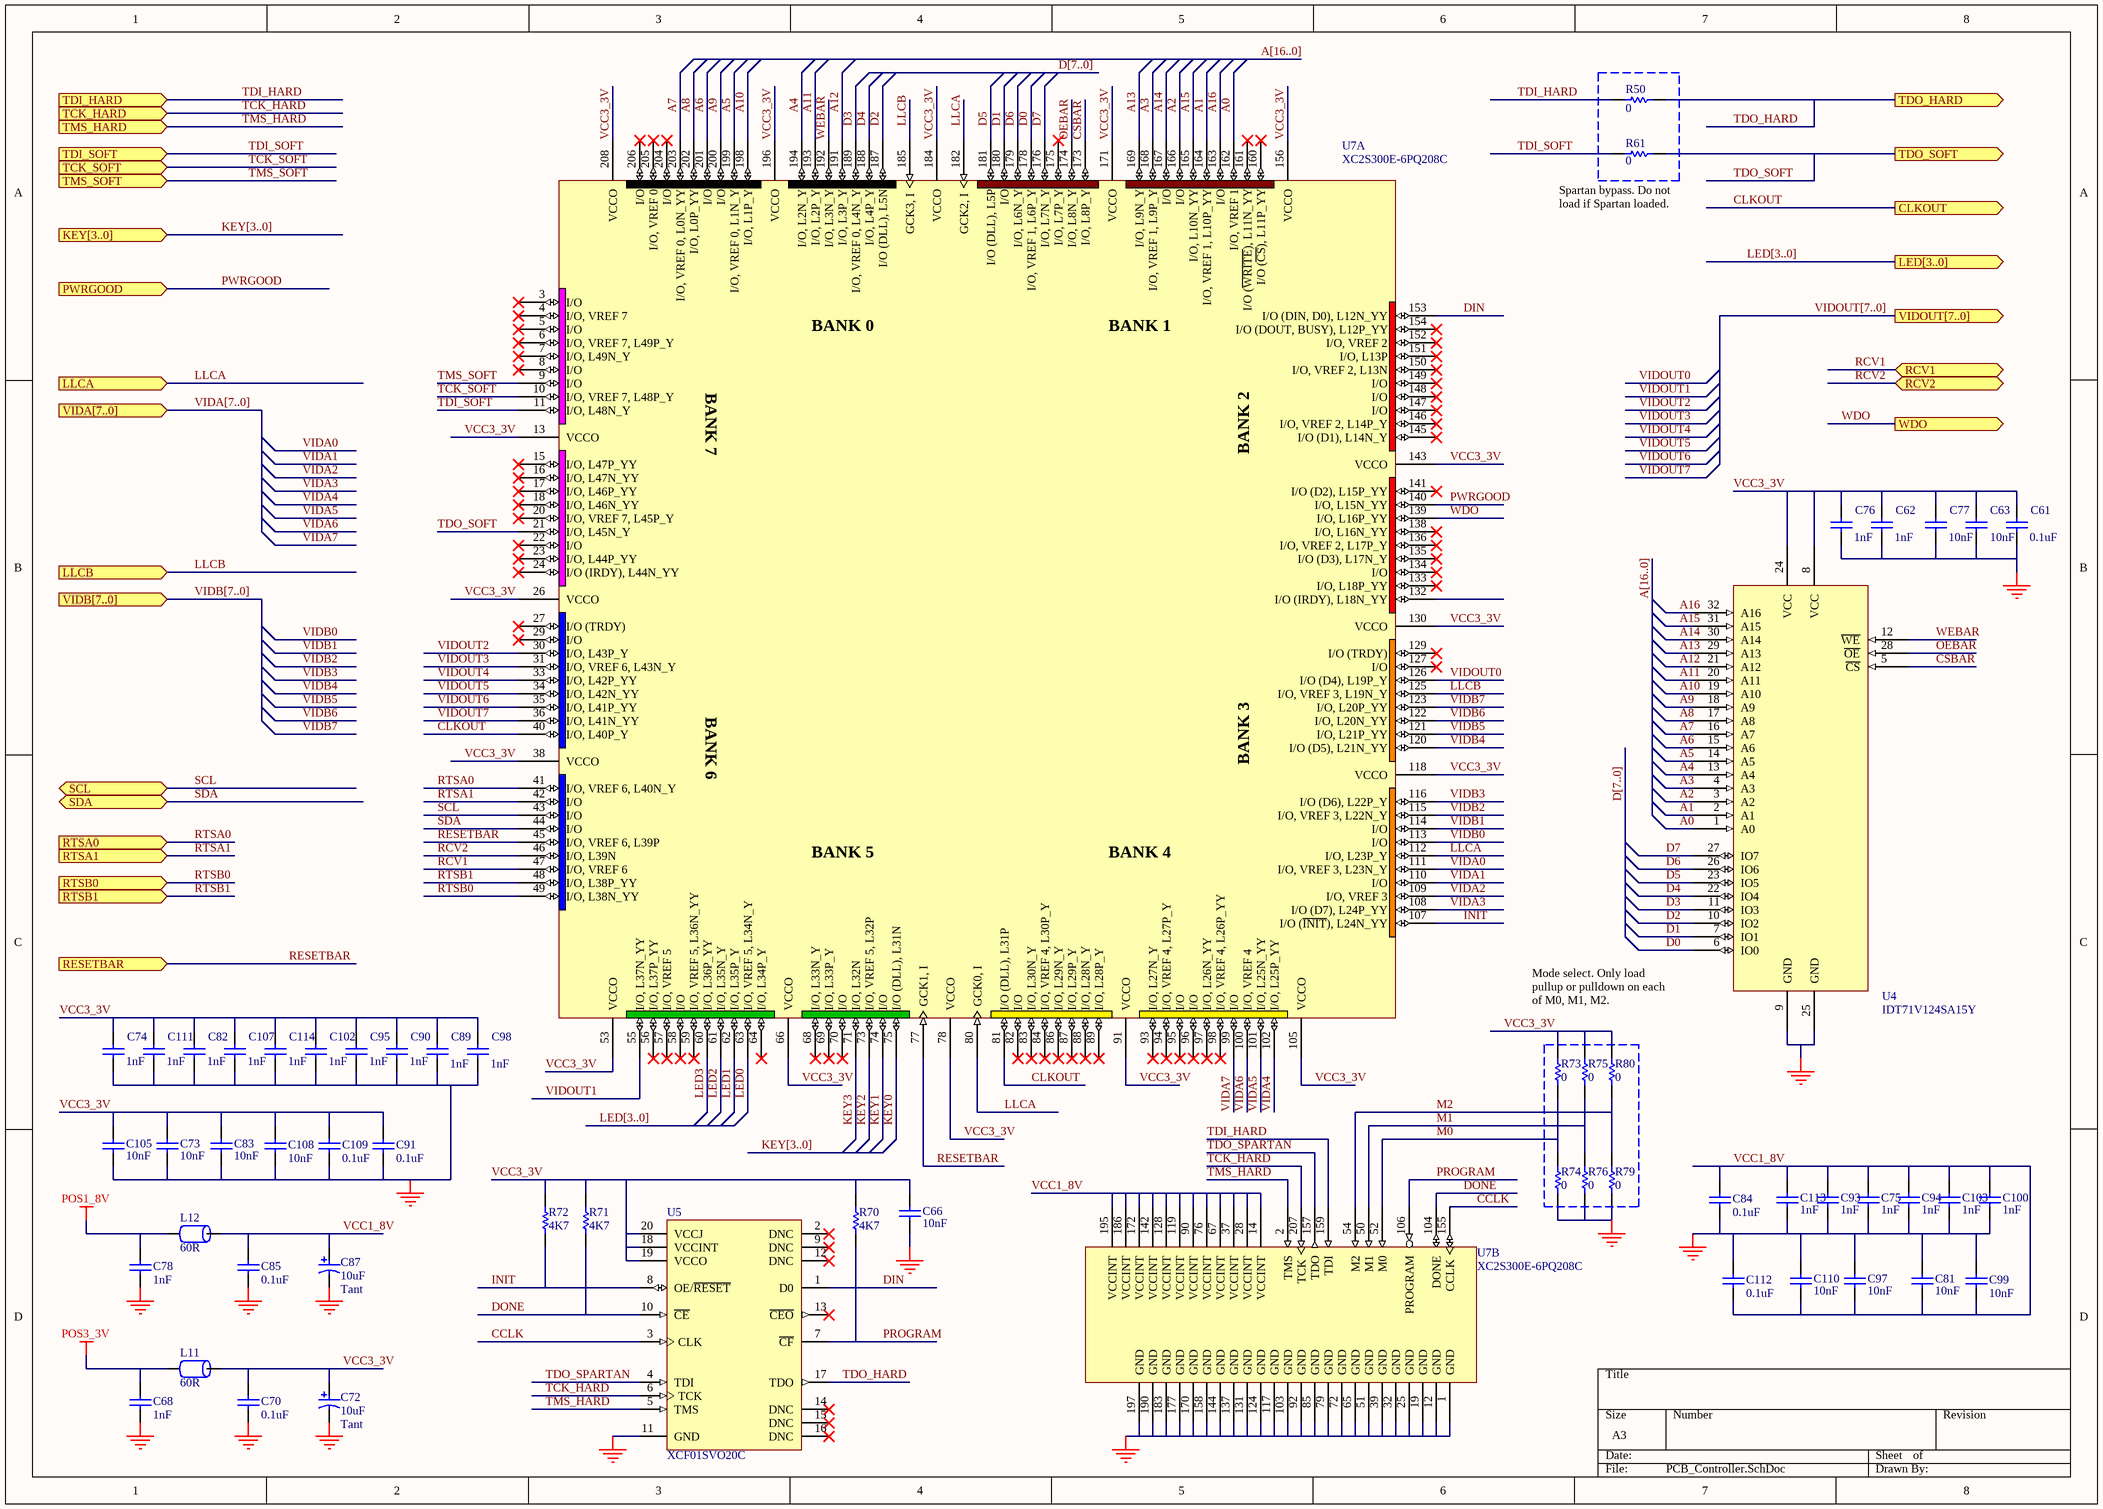
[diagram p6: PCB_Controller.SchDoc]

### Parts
C61  0.1uF  [CC2012-0805]
C62  1nF  [CC2012-0805]
C63  10nF  [CC2012-0805]
C66  10nF  [CC2012-0805]
C68  1nF  [CC2012-0805]
C70  0.1uF  [CC2012-0805]
C72  10uF  Capacitor Type: Tant  [MCCT-B]
C73  10nF  [CC2012-0805]
C74  1nF  [CC2012-0805]
C75  1nF  [CC2012-0805]
C76  1nF  [CC2012-0805]
C77  10nF  [CC2012-0805]
C78  1nF  [CC2012-0805]
C81  10nF  [CC2012-0805]
C82  1nF  [CC2012-0805]
C83  10nF  [CC2012-0805]
C84  0.1uF  [CC2012-0805]
C85  0.1uF  [CC2012-0805]
C87  10uF  Capacitor Type: Tant  [MCCT-B]
C89  1nF  [CC2012-0805]
C90  1nF  [CC2012-0805]
C91  0.1uF  [CC2012-0805]
C93  1nF  [CC2012-0805]
C94  1nF  [CC2012-0805]
C95  1nF  [CC2012-0805]
C97  10nF  [CC2012-0805]
C98  1nF  [CC2012-0805]
C99  10nF  [CC2012-0805]
C100  1nF  [CC2012-0805]
C102  1nF  [CC2012-0805]
C103  1nF  [CC2012-0805]
C105  10nF  [CC2012-0805]
C107  1nF  [CC2012-0805]
C108  10nF  [CC2012-0805]
C109  0.1uF  [CC2012-0805]
C110  10nF  [CC2012-0805]
C111  1nF  [CC2012-0805]
C112  0.1uF  [CC2012-0805]
C113  1nF  [CC2012-0805]
C114  1nF  [CC2012-0805]
L11  60R  [CC2012-0805]
L12  60R  [CC2012-0805]
R50  0  [CC2012-0805]
R61  0  [CC2012-0805]
R70  4K7  [CC2012-0805]
R71  4K7  [CC2012-0805]
R72  4K7  [CC2012-0805]
R73  0  [CC2012-0805]
R74  0  [CC2012-0805]
R75  0  [CC2012-0805]
R76  0  [CC2012-0805]
R79  0  [CC2012-0805]
R80  0  [CC2012-0805]
U4  IDT71V124SA15Y  [SO-J32]
U5  XCF01SVO20C  [VO20]
U7  XC2S300E-6PQ208C  [F-QFP28X28-G208/P.5N]  (parts A,B of 2)

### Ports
CLKOUT (out), KEY[3..0] (in), LED[3..0] (out), LLCA (in), LLCB (in), PWRGOOD (in), RCV1 (bidir), RCV2 (bidir), RESETBAR (in), RTSA0 (in), RTSA1 (in), RTSB0 (in), RTSB1 (in), SCL (bidir), SDA (bidir), TCK_HARD (in), TCK_SOFT (in), TDI_HARD (in), TDI_SOFT (in), TDO_HARD (out), TDO_SOFT (out), TMS_HARD (in), TMS_SOFT (in), VIDA[7..0] (in), VIDB[7..0] (in), VIDOUT[7..0] (out), WDO (out)

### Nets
GND: C61.2 C62.2 C63.2 C66.2 C68.2 C70.2 C72.2 C73.2 C74.2 C75.2 C76.2 C77.2 C78.2 C81.1 C82.2 C83.2 C84.2 C85.2 C87.2 C89.2 C90.2 C91.2 C93.2 C94.2 C95.2 C97.1 C98.2 C99.1 C100.2 C102.2 C103.2 C105.2 C107.2 C108.2 C109.2 C110.1 C111.2 C112.1 C113.2 C114.2 R74.2 R76.2 R79.2 U4.9(GND) U4.25(GND) U5.11(GND) U7.1(GND) U7.12(GND) U7.19(GND) U7.25(GND) U7.32(GND) U7.39(GND) U7.51(GND) U7.65(GND) U7.72(GND) U7.79(GND) U7.85(GND) U7.92(GND) U7.103(GND) U7.117(GND) U7.124(GND) U7.131(GND) U7.137(GND) U7.144(GND) U7.158(GND) U7.170(GND) U7.177(GND) U7.183(GND) U7.190(GND) U7.197(GND)
POS1_8V: C78.1 L12.1
POS3_3V: C68.1 L11.1
A0: U4.1(A0) U7.162(I/O,_VREF_1)
A1: U4.2(A1) U7.164(I/O,_VREF_1,_L10P_YY)
A2: U4.3(A2) U7.166(I/O)
A3: U4.4(A3) U7.168(I/O,_VREF_1,_L9P_Y)
A4: U4.13(A4) U7.194(I/O,_L2N_Y)
A5: U4.14(A5) U7.199(I/O,_VREF_0,_L1N_Y)
A6: U4.15(A6) U7.201(I/O)
A7: U4.16(A7) U7.203(I/O,_VREF_0,_L0N_YY)
A8: U4.17(A8) U7.202(I/O,_L0P_YY)
A9: U4.18(A9) U7.200(I/O)
A10: U4.19(A10) U7.198(I/O,_L1P_Y)
A11: U4.20(A11) U7.193(I/O,_L2P_Y)
A12: U4.21(A12) U7.191(I/O,_L3P_Y)
A13: U4.29(A13) U7.169(I/O,_L9N_Y)
A14: U4.30(A14) U7.167(I/O)
A15: U4.31(A15) U7.165(I/O,_L10N_YY)
A16: U4.32(A16) U7.163(I/O)
CCLK: U5.3(CLK) U7.155(CCLK)
CLKOUT: U7.40(I/O,_L40P_Y) U7.81(I/O_(DLL),_L31P) ; port CLKOUT
CSBAR: U4.5(~{CS}) U7.173(I/O,_L8P_Y)
D0: U4.6(IO0) U7.178(I/O,_VREF_1,_L6P_Y)
D1: U4.7(IO1) U7.180(I/O)
D2: U4.10(IO2) U7.187(I/O_(DLL),_L5N)
D3: U4.11(IO3) U7.189(I/O,_VREF_0,_L4N_Y)
D4: U4.22(IO4) U7.188(I/O,_L4P_Y)
D5: U4.23(IO5) U7.181(I/O_(DLL),_L5P)
D6: U4.26(IO6) U7.179(I/O,_L6N_Y)
D7: U4.27(IO7) U7.176(I/O,_L7N_Y)
DIN: U5.1(D0) U7.153(I/O_(DIN,_D0),_L12N_YY)
DONE: R71.2 U5.10(~{CE}) U7.104(DONE)
INIT: R72.2 U5.8(OE/~{RESET}) U7.107(I/O_(~{INIT}),_L24N_YY)
KEY0: U7.75(I/O_(DLL),_L31N)
KEY1: U7.74(I/O)
KEY2: U7.73(I/O,_VREF_5,_L32P)
KEY3: U7.71(I/O,_L32N)
LED0: U7.63(I/O,_VREF_5,_L34N_Y)
LED1: U7.62(I/O,_L35P_Y)
LED2: U7.61(I/O,_L35N_Y)
LED3: U7.60(I/O,_L36P_YY)
LLCA: U7.80(GCK0,_I) U7.112(I/O,_L23P_Y) U7.182(GCK2,_I) ; port LLCA
LLCB: U7.125(I/O,_VREF_3,_L19N_Y) U7.185(GCK3,_I) ; port LLCB
M0: R73.2 R74.1 U7.52(M0)
M1: R75.2 R76.1 U7.50(M1)
M2: R79.1 R80.2 U7.54(M2)
OEBAR: U4.28(~{OE}) U7.174(I/O,_L8N_Y)
PROGRAM: R70.2 U5.7(~{CF}) U7.106(PROGRAM)
PWRGOOD: U7.140(I/O,_L15N_YY) ; port PWRGOOD
RCV1: U7.47(I/O,_VREF_6) ; port RCV1
RCV2: U7.46(I/O,_L39N) ; port RCV2
RESETBAR: U7.45(I/O,_VREF_6,_L39P) U7.77(GCK1,_I) ; port RESETBAR
RTSA0: U7.41(I/O,_VREF_6,_L40N_Y) ; port RTSA0
RTSA1: U7.42(I/O) ; port RTSA1
RTSB0: U7.49(I/O,_L38N_YY) ; port RTSB0
RTSB1: U7.48(I/O,_L38P_YY) ; port RTSB1
SCL: U7.43(I/O) ; port SCL
SDA: U7.44(I/O) ; port SDA
TCK_HARD: U5.6(TCK) U7.207(TCK) ; port TCK_HARD
TCK_SOFT: U7.10(I/O,_VREF_7,_L48P_Y) ; port TCK_SOFT
TDI_HARD: R50.1 U7.159(TDI) ; port TDI_HARD
TDI_SOFT: R61.1 U7.11(I/O,_L48N_Y) ; port TDI_SOFT
TDO_HARD: R50.2 U5.17(TDO) ; port TDO_HARD  [project net TDO_CONTROLLER]
TDO_SOFT: R61.2 U7.21(I/O,_L45N_Y) ; port TDO_SOFT
TDO_SPARTAN: U5.4(TDI) U7.157(TDO)
TMS_HARD: U5.5(TMS) U7.2(TMS) ; port TMS_HARD
TMS_SOFT: U7.9(I/O) ; port TMS_SOFT
VCC1_8V: C75.1 C81.2 C84.1 C85.1 C87.1 C93.1 C94.1 C97.2 C99.2 C100.1 C103.1 C110.2 C112.2 C113.1 L12.2 U7.14(VCCINT) U7.28(VCCINT) U7.37(VCCINT) U7.67(VCCINT) U7.76(VCCINT) U7.90(VCCINT) U7.119(VCCINT) U7.128(VCCINT) U7.142(VCCINT) U7.172(VCCINT) U7.186(VCCINT) U7.195(VCCINT)
VCC3_3V: C61.1 C62.1 C63.1 C66.1 C70.1 C72.1 C73.1 C74.1 C76.1 C77.1 C82.1 C83.1 C89.1 C90.1 C91.1 C95.1 C98.1 C102.1 C105.1 C107.1 C108.1 C109.1 C111.1 C114.1 L11.2 R70.1 R71.1 R72.1 R73.1 R75.1 R80.1 U4.8(VCC) U4.24(VCC) U5.18(VCCINT) U5.19(VCCO) U5.20(VCCJ) U7.13(VCCO) U7.26(VCCO) U7.38(VCCO) U7.53(VCCO) U7.66(VCCO) U7.78(VCCO) U7.91(VCCO) U7.105(VCCO) U7.118(VCCO) U7.130(VCCO) U7.143(VCCO) U7.156(VCCO) U7.171(VCCO) U7.184(VCCO) U7.196(VCCO) U7.208(VCCO)
VIDA0: U7.111(I/O,_VREF_3,_L23N_Y)  [project net MPA0]
VIDA1: U7.110(I/O)  [project net MPA1]
VIDA2: U7.109(I/O,_VREF_3)  [project net MPA2]
VIDA3: U7.108(I/O_(D7),_L24P_YY)  [project net MPA3]
VIDA4: U7.102(I/O,_L25P_YY)  [project net MPA4]
VIDA5: U7.101(I/O,_L25N_YY)  [project net MPA5]
VIDA6: U7.100(I/O,_VREF_4)  [project net MPA6]
VIDA7: U7.99(I/O)  [project net MPA7]
VIDB0: U7.113(I/O)  [project net MPB0]
VIDB1: U7.114(I/O)  [project net MPB1]
VIDB2: U7.115(I/O,_VREF_3,_L22N_Y)  [project net MPB2]
VIDB3: U7.116(I/O_(D6),_L22P_Y)  [project net MPB3]
VIDB4: U7.120(I/O_(D5),_L21N_YY)  [project net MPB4]
VIDB5: U7.121(I/O,_L21P_YY)  [project net MPB5]
VIDB6: U7.122(I/O,_L20N_YY)  [project net MPB6]
VIDB7: U7.123(I/O,_L20P_YY)  [project net MPB7]
VIDOUT0: U7.126(I/O_(D4),_L19P_Y)  [project net MPOUT0]
VIDOUT1: U7.55(I/O,_L37N_YY)  [project net MPOUT1]
VIDOUT2: U7.30(I/O,_L43P_Y)  [project net MPOUT2]
VIDOUT3: U7.31(I/O,_VREF_6,_L43N_Y)  [project net MPOUT3]
VIDOUT4: U7.33(I/O,_L42P_YY)  [project net MPOUT4]
VIDOUT5: U7.34(I/O,_L42N_YY)  [project net MPOUT5]
VIDOUT6: U7.35(I/O,_L41P_YY)  [project net MPOUT6]
VIDOUT7: U7.36(I/O,_L41N_YY)  [project net MPOUT7]
WDO: U7.139(I/O,_L16P_YY) ; port WDO  [project net WDOG]
WEBAR: U4.12(~{WE}) U7.192(I/O,_L3N_Y)

Not connected (* = marked no-connect by the designer): U5 2(DNC)* 9(DNC)* 12(DNC)* 13(~{CEO})* 14(DNC)* 15(DNC)* 16(DNC)*; U7 3(I/O)* 4(I/O,_VREF_7)* 5(I/O)* 6(I/O,_VREF_7,_L49P_Y)* 7(I/O,_L49N_Y)* 8(I/O)* 15(I/O,_L47P_YY)* 16(I/O,_L47N_YY)* 17(I/O,_L46P_YY)* 18(I/O,_L46N_YY)* 20(I/O,_VREF_7,_L45P_Y)* 22(I/O)* 23(I/O,_L44P_YY)* 24(I/O_(IRDY),_L44N_YY)* 27(I/O_(TRDY))* 29(I/O)* 56(I/O,_L37P_YY)* 57(I/O,_VREF_5)* 58(I/O)* 59(I/O,_VREF_5,_L36N_YY)* 64(I/O,_L34P_Y)* 68(I/O,_L33N_Y)* 69(I/O,_L33P_Y)* 70(I/O)* 82(I/O)* 83(I/O,_L30N_Y)* 84(I/O,_VREF_4,_L30P_Y)* 86(I/O,_L29N_Y)* 87(I/O,_L29P_Y)* 88(I/O,_L28N_Y)* 89(I/O,_L28P_Y)* 93(I/O,_L27N_Y)* 94(I/O,_VREF_4,_L27P_Y)* 95(I/O)* 96(I/O)* 97(I/O,_L26N_YY)* 98(I/O,_VREF_4,_L26P_YY)* 127(I/O)* 129(I/O_(TRDY))* 132(I/O_(IRDY),_L18N_YY) 133(I/O,_L18P_YY)* 134(I/O)* 135(I/O_(D3),_L17N_Y)* 136(I/O,_VREF_2,_L17P_Y)* 138(I/O,_L16N_YY)* 141(I/O_(D2),_L15P_YY)* 145(I/O_(D1),_L14N_Y)* 146(I/O,_VREF_2,_L14P_Y)* 147(I/O)* 148(I/O)* 149(I/O)* 150(I/O,_VREF_2,_L13N)* 151(I/O,_L13P)* 152(I/O,_VREF_2)* 154(I/O_(DOUT,_BUSY),_L12P_YY)* 160(I/O_(~{CS}),_L11P_YY)* 161(I/O_(~{WRITE}),_L11N_YY)* 175(I/O,_L7P_Y)* 204(I/O)* 205(I/O,_VREF_0)* 206(I/O)*

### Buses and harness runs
bus A[16..0]
bus D[7..0]
bus KEY[3..0]
bus KEY[3..0] = port KEY[3..0]
bus LED[3..0]
bus LED[3..0] = port LED[3..0]
bus VIDA[7..0] = port VIDA[7..0]
bus VIDB[7..0] = port VIDB[7..0]
bus VIDOUT[7..0] = port VIDOUT[7..0]

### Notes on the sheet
- (near R61) Spartan bypass. Do not load if Spartan loaded.
- Mode select. Only load pullup or pulldown on each of M0, M1, M2.

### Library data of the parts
C61-C63 C66 C68 C70 C73-C78 C81-C85 C89-C91 C93-C95 C97-C100 C102 C103 C105 C107-C114 = CAP: Capacitor; Fitted: True
C72 C87 = CAP_POLAR: Polar Capacitor; Fitted: True
L11 L12 = FERRITE_BEAD: BMB Series Ferrite Chip Bead
R50 R61 R70-R76 R79 R80 = RES: Resistor; Fitted: True
U4 = IDT71V124SA15Y: 128K x 8 bit Fast Static RAM; Fitted: True
U5 = XCF01SVO20C: XCF00S Series, Platform Flash In-System Programmable Configuration 3.3V PROM, 1-Megabit, Commercial Grade; Manufacturer: Xilinx; Package Information: Latest Revision: ver1.0, May-2003; Class I: Memory; Code - JEDEC: MO-153-AC; Fitted: True
U7 = XC2S300E-6PQ208C: Spartan-IIE 1.8V FPGA, 208-Pin PQFP, Standard Performance, Commercial Grade; Package Information: Latest Revision: ver1.1, Oct-2002; Code - JEDEC: MS-029-FA-1

## Sheet PCB_Power.SchDoc
size A4; DocumentNumber: 5; SheetNumber: 5; SheetTotal: 8
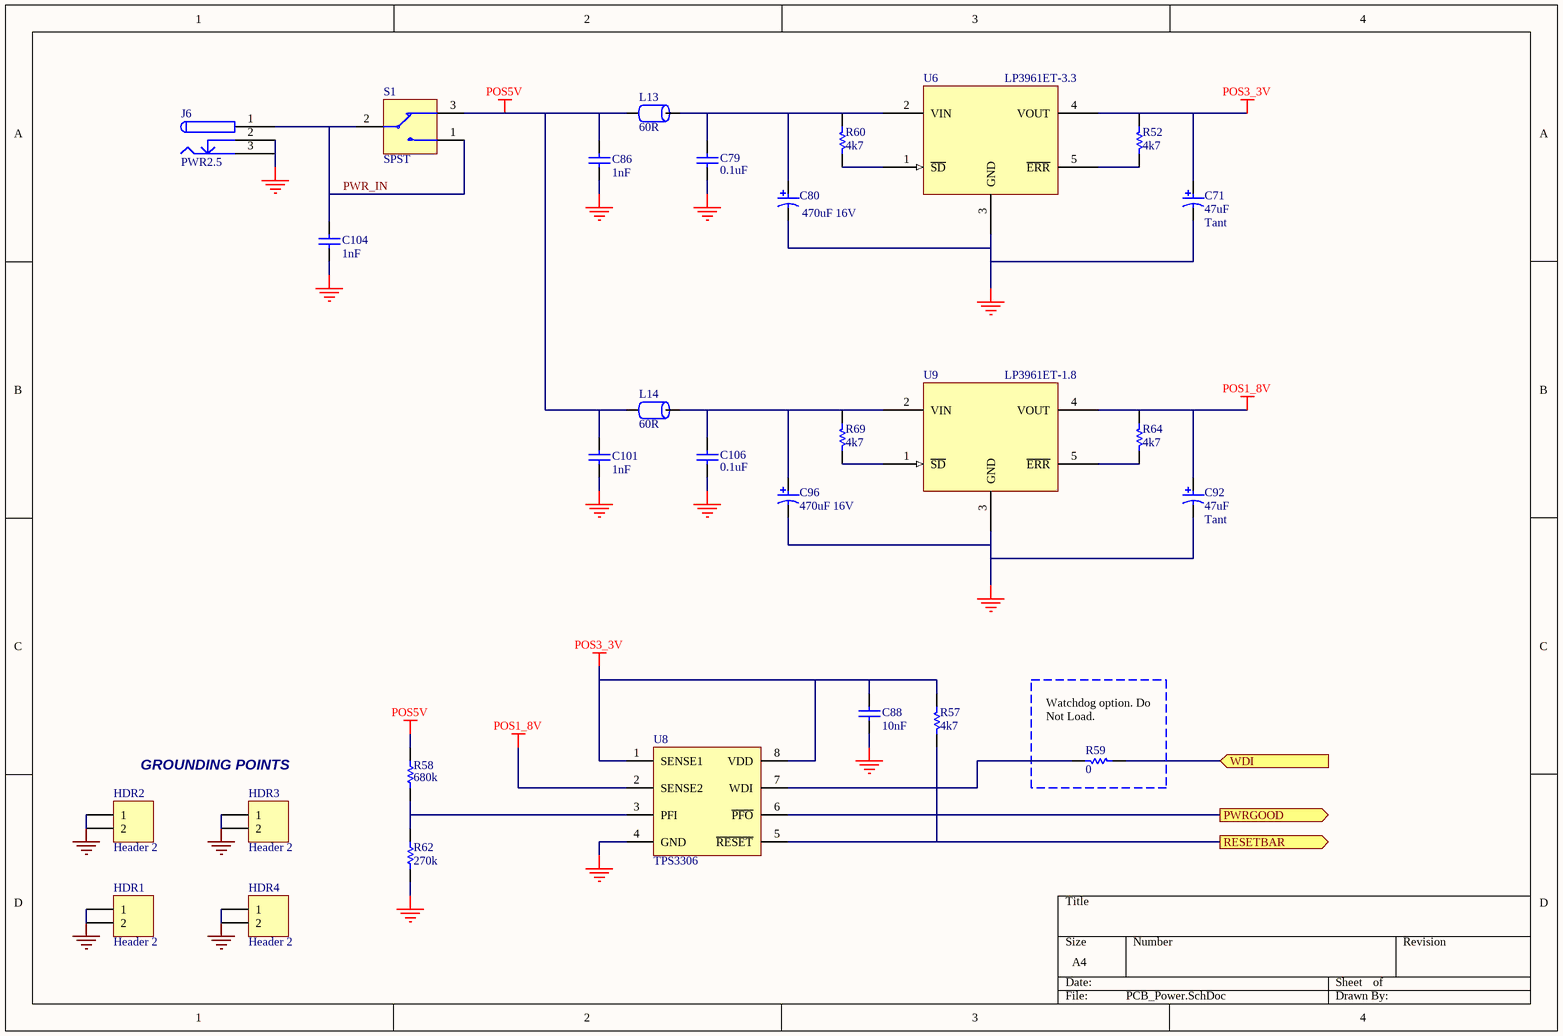
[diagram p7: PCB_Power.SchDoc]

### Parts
C71  47uF  Capacitor Type: Tant  [MCCTD]
C79  0.1uF  [CC2012-0805]
C80  470uF 16V  [RB8/3.5]
C86  1nF  [CC2012-0805]
C88  10nF  [CC2012-0805]
C92  47uF  Capacitor Type: Tant  [MCCTD]
C96  470uF 16V  [RB8/3.5]
C101  1nF  [CC2012-0805]
C104  1nF  [CC2012-0805]
C106  0.1uF  [CC2012-0805]
HDR1  Header 2  [HDR1X2]
HDR2  Header 2  [HDR1X2]
HDR3  Header 2  [HDR1X2]
HDR4  Header 2  [HDR1X2]
J6  PWR2.5  [PWR2.5]
L13  60R  [CC2012-0805]
L14  60R  [CC2012-0805]
R52  4k7  [CC2012-0805]
R57  4k7  [CC2012-0805]
R58  680k  [CC2012-0805]
R59  0  [CC2012-0805]
R60  4k7  [CC2012-0805]
R62  270k  [CC2012-0805]
R64  4k7  [CC2012-0805]
R69  4k7  [CC2012-0805]
S1  SPST  [PCB_SWITCH]
U6  LP3961ET-3.3  [TO220-5V]
U8  TPS3306  [SOIC8]
U9  LP3961ET-1.8  [TO220-5V]

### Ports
PWRGOOD (out), RESETBAR (out), WDI (in)

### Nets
GND: C71.2 C79.2 C80.2 C86.2 C88.2 C92.2 C96.2 C101.2 C104.2 C106.2 HDR1.1 HDR1.2 HDR2.1 HDR2.2 HDR3.1 HDR3.2 HDR4.1 HDR4.2 J6.2 J6.3 R62.2 U6.3(GND) U8.4(GND) U9.3(GND)
POS1_8V: C92.1 R64.2 U8.2(SENSE2) U9.4(VOUT)
POS3_3V: C71.1 C88.1 R52.2 R57.2 U6.4(VOUT) U8.1(SENSE1) U8.8(VDD)
POS5V: C86.1 C101.1 L13.1 L14.1 R58.1 S1.3
PWR_IN: C104.1 J6.1 S1.1 S1.2
PWRGOOD: U8.6(~{PFO}) ; port PWRGOOD
RESETBAR: R57.1 U8.5(~{RESET}) ; port RESETBAR
WDOG: R59.1 ; port WDI
NetC79_1: C79.1 C80.1 L13.2 R60.2 U6.2(VIN)
NetC96_1: C96.1 C106.1 L14.2 R69.2 U9.2(VIN)
NetR52_1: R52.1 U6.5(~{ERR})
NetR58_2: R58.2 R62.1 U8.3(PFI)
NetR59_2: R59.2 U8.7(WDI)
NetR60_1: R60.1 U6.1(~{SD})
NetR64_1: R64.1 U9.5(~{ERR})
NetR69_1: R69.1 U9.1(~{SD})

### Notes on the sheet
- GROUNDING POINTS
- (near R59) Watchdog option. Do Not Load.

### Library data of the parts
C71 C80 C92 C96 = CAP_POLAR: Polar Capacitor; Fitted: True
C79 C86 C88 C101 C104 C106 = CAP: Capacitor; Fitted: True
HDR1-HDR4 = Header 2: Header, 2-Pin; Manufacturer: Generic Components; Class I: Connector; Fitted: True
J6 = PWR2.5: Low Voltage Power Supply Sonnector; Fitted: True
L13 L14 = FERRITE_BEAD: BMB Series Ferrite Chip Bead
R52 R57-R60 R62 R64 R69 = RES: Resistor; Fitted: True
S1 = PCB_MOUNT_SWITCH: SPDT Subminiature Toggle Switch; Fitted: True
U6 U9 = LP3961ET: 800mA Fast UL Dropout Regulator
U8 = TPS3306: TI Dual Voltage MPU Supervisory Circuit

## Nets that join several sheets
GND: PCB_DecoderA (34 pins), PCB_DecoderB (33 pins), PCB_Headers (JP2.20 JP3.20 JP4.9 JP4.10), PCB_Encoder (34 pins), PCB_IO (13 pins), PCB_Controller (70 pins), PCB_Power (24 pins)
POS1_8V: PCB_Controller (C78.1 L12.1), PCB_Power (C92.1 R64.2 U8.2 U9.4)
POS3_3V: PCB_DecoderA (C11.1 C56.1 L2.1 L9.1), PCB_DecoderB (C10.1 C53.1 L1.1 L8.1), PCB_Encoder (C32.1 C69.1 L6.1 L10.1), PCB_IO (8 pins), PCB_Controller (C68.1 L11.1), PCB_Power (7 pins)
POS5V: PCB_IO (LED5.1), PCB_Power (6 pins)
AIN0: PCB_DecoderA (R8.1), PCB_DecoderB (R17.1), PCB_IO (J5.1)
AIN1: PCB_DecoderA (R6.1), PCB_DecoderB (R15.1), PCB_IO (J4.1)
AIN2: PCB_DecoderA (R4.1), PCB_DecoderB (R13.1), PCB_IO (J3.1)
AIN3: PCB_DecoderA (R2.1), PCB_DecoderB (R11.1), PCB_IO (J1.1)
CLKOUT: PCB_Headers (JP3.10), PCB_Encoder (R49.1 U3.4), PCB_Controller (U7.40 U7.81)
KEY0: PCB_IO (R78.2 SW4.3 SW4.4), PCB_Controller (U7.75)
KEY1: PCB_IO (R67.2 SW3.3 SW3.4), PCB_Controller (U7.74)
KEY2: PCB_IO (R63.2 SW2.3 SW2.4), PCB_Controller (U7.73)
KEY3: PCB_IO (R55.2 SW1.3 SW1.4), PCB_Controller (U7.71)
LED0: PCB_IO (R68.2), PCB_Controller (U7.63)
LED1: PCB_IO (R65.2), PCB_Controller (U7.62)
LED2: PCB_IO (R56.2), PCB_Controller (U7.61)
LED3: PCB_IO (R53.2), PCB_Controller (U7.60)
LLCA: PCB_DecoderA (R21.1), PCB_Headers (JP2.10), PCB_Controller (U7.80 U7.112 U7.182)
LLCB: PCB_DecoderB (R22.1), PCB_Headers (JP2.19), PCB_Controller (U7.125 U7.185)
MPA0: PCB_DecoderA (R30.1), PCB_Headers (JP2.2), PCB_Controller (U7.111)
MPA1: PCB_DecoderA (R40.1), PCB_Headers (JP2.3), PCB_Controller (U7.110)
MPA2: PCB_DecoderA (R31.1), PCB_Headers (JP2.4), PCB_Controller (U7.109)
MPA3: PCB_DecoderA (R41.1), PCB_Headers (JP2.5), PCB_Controller (U7.108)
MPA4: PCB_DecoderA (R32.1), PCB_Headers (JP2.6), PCB_Controller (U7.102)
MPA5: PCB_DecoderA (R42.1), PCB_Headers (JP2.7), PCB_Controller (U7.101)
MPA6: PCB_DecoderA (R33.1), PCB_Headers (JP2.8), PCB_Controller (U7.100)
MPA7: PCB_DecoderA (R43.1), PCB_Headers (JP2.9), PCB_Controller (U7.99)
MPB0: PCB_DecoderB (R35.1), PCB_Headers (JP2.11), PCB_Controller (U7.113)
MPB1: PCB_DecoderB (R36.1), PCB_Headers (JP2.12), PCB_Controller (U7.114)
MPB2: PCB_DecoderB (R37.1), PCB_Headers (JP2.13), PCB_Controller (U7.115)
MPB3: PCB_DecoderB (R44.1), PCB_Headers (JP2.14), PCB_Controller (U7.116)
MPB4: PCB_DecoderB (R38.1), PCB_Headers (JP2.15), PCB_Controller (U7.120)
MPB5: PCB_DecoderB (R45.1), PCB_Headers (JP2.16), PCB_Controller (U7.121)
MPB6: PCB_DecoderB (R39.1), PCB_Headers (JP2.17), PCB_Controller (U7.122)
MPB7: PCB_DecoderB (R46.1), PCB_Headers (JP2.18), PCB_Controller (U7.123)
MPOUT0: PCB_Headers (JP3.2), PCB_Encoder (U3.16), PCB_Controller (U7.126)
MPOUT1: PCB_Headers (JP3.3), PCB_Encoder (U3.15), PCB_Controller (U7.55)
MPOUT2: PCB_Headers (JP3.4), PCB_Encoder (U3.14), PCB_Controller (U7.30)
MPOUT3: PCB_Headers (JP3.5), PCB_Encoder (U3.13), PCB_Controller (U7.31)
MPOUT4: PCB_Headers (JP3.6), PCB_Encoder (U3.12), PCB_Controller (U7.33)
MPOUT5: PCB_Headers (JP3.7), PCB_Encoder (U3.11), PCB_Controller (U7.34)
MPOUT6: PCB_Headers (JP3.8), PCB_Encoder (U3.10), PCB_Controller (U7.35)
MPOUT7: PCB_Headers (JP3.9), PCB_Encoder (U3.9), PCB_Controller (U7.36)
PWRGOOD: PCB_Controller (U7.140), PCB_Power (U8.6)
RCV1: PCB_Headers (JP3.15), PCB_Encoder (U3.7), PCB_Controller (U7.47)
RCV2: PCB_Headers (JP3.16), PCB_Encoder (U3.8), PCB_Controller (U7.46)
RESETBAR: PCB_DecoderA (U1.24 U1.58), PCB_DecoderB (U2.24 U2.58), PCB_Headers (JP3.17), PCB_Encoder (U3.40), PCB_Controller (U7.45 U7.77), PCB_Power (R57.1 U8.5)
RTSA0: PCB_DecoderA (U1.28), PCB_Headers (JP3.11), PCB_Controller (U7.41)
RTSA1: PCB_DecoderA (U1.29), PCB_Headers (JP3.12), PCB_Controller (U7.42)
RTSB0: PCB_DecoderB (U2.28), PCB_Headers (JP3.13), PCB_Controller (U7.49)
RTSB1: PCB_DecoderB (U2.29), PCB_Headers (JP3.14), PCB_Controller (U7.48)
SCL: PCB_DecoderA (U1.63), PCB_DecoderB (U2.63), PCB_Headers (JP3.19), PCB_Encoder (R47.1 U3.41), PCB_Controller (U7.43)
SDA: PCB_DecoderA (U1.62), PCB_DecoderB (U2.62), PCB_Headers (JP3.18), PCB_Encoder (R48.1 U3.42), PCB_Controller (U7.44)
TCK: PCB_Top (R54.2), PCB_DecoderA (U1.59), PCB_DecoderB (U2.59)
TCK_HARD: PCB_Top (R54.1), PCB_Headers (JP4.3), PCB_Controller (U5.6 U7.207)
TCK_SOFT: PCB_Headers (JP4.7), PCB_Controller (U7.10)
TDI_B: PCB_DecoderA (R19.1 R20.2), PCB_DecoderB (R10.1 U2.3)
TDI_HARD: PCB_Headers (JP4.1), PCB_Controller (R50.1 U7.159)
TDI_SOFT: PCB_Headers (JP4.5), PCB_Controller (R61.1 U7.11)
TDO_CONTROLLER: PCB_DecoderA (R20.1 U1.3), PCB_Controller (R50.2 U5.17)
TDO_HARD: PCB_DecoderB (R10.2 R18.1), PCB_Headers (JP4.2)
TDO_SOFT: PCB_Headers (R66.1), PCB_Controller (R61.2 U7.21)
TMS: PCB_Top (R51.2), PCB_DecoderA (U1.4), PCB_DecoderB (U2.4)
TMS_HARD: PCB_Top (R51.1), PCB_Headers (JP4.4), PCB_Controller (U5.5 U7.2)
TMS_SOFT: PCB_Headers (JP4.8), PCB_Controller (U7.9)
WDOG: PCB_Controller (U7.139), PCB_Power (R59.1)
